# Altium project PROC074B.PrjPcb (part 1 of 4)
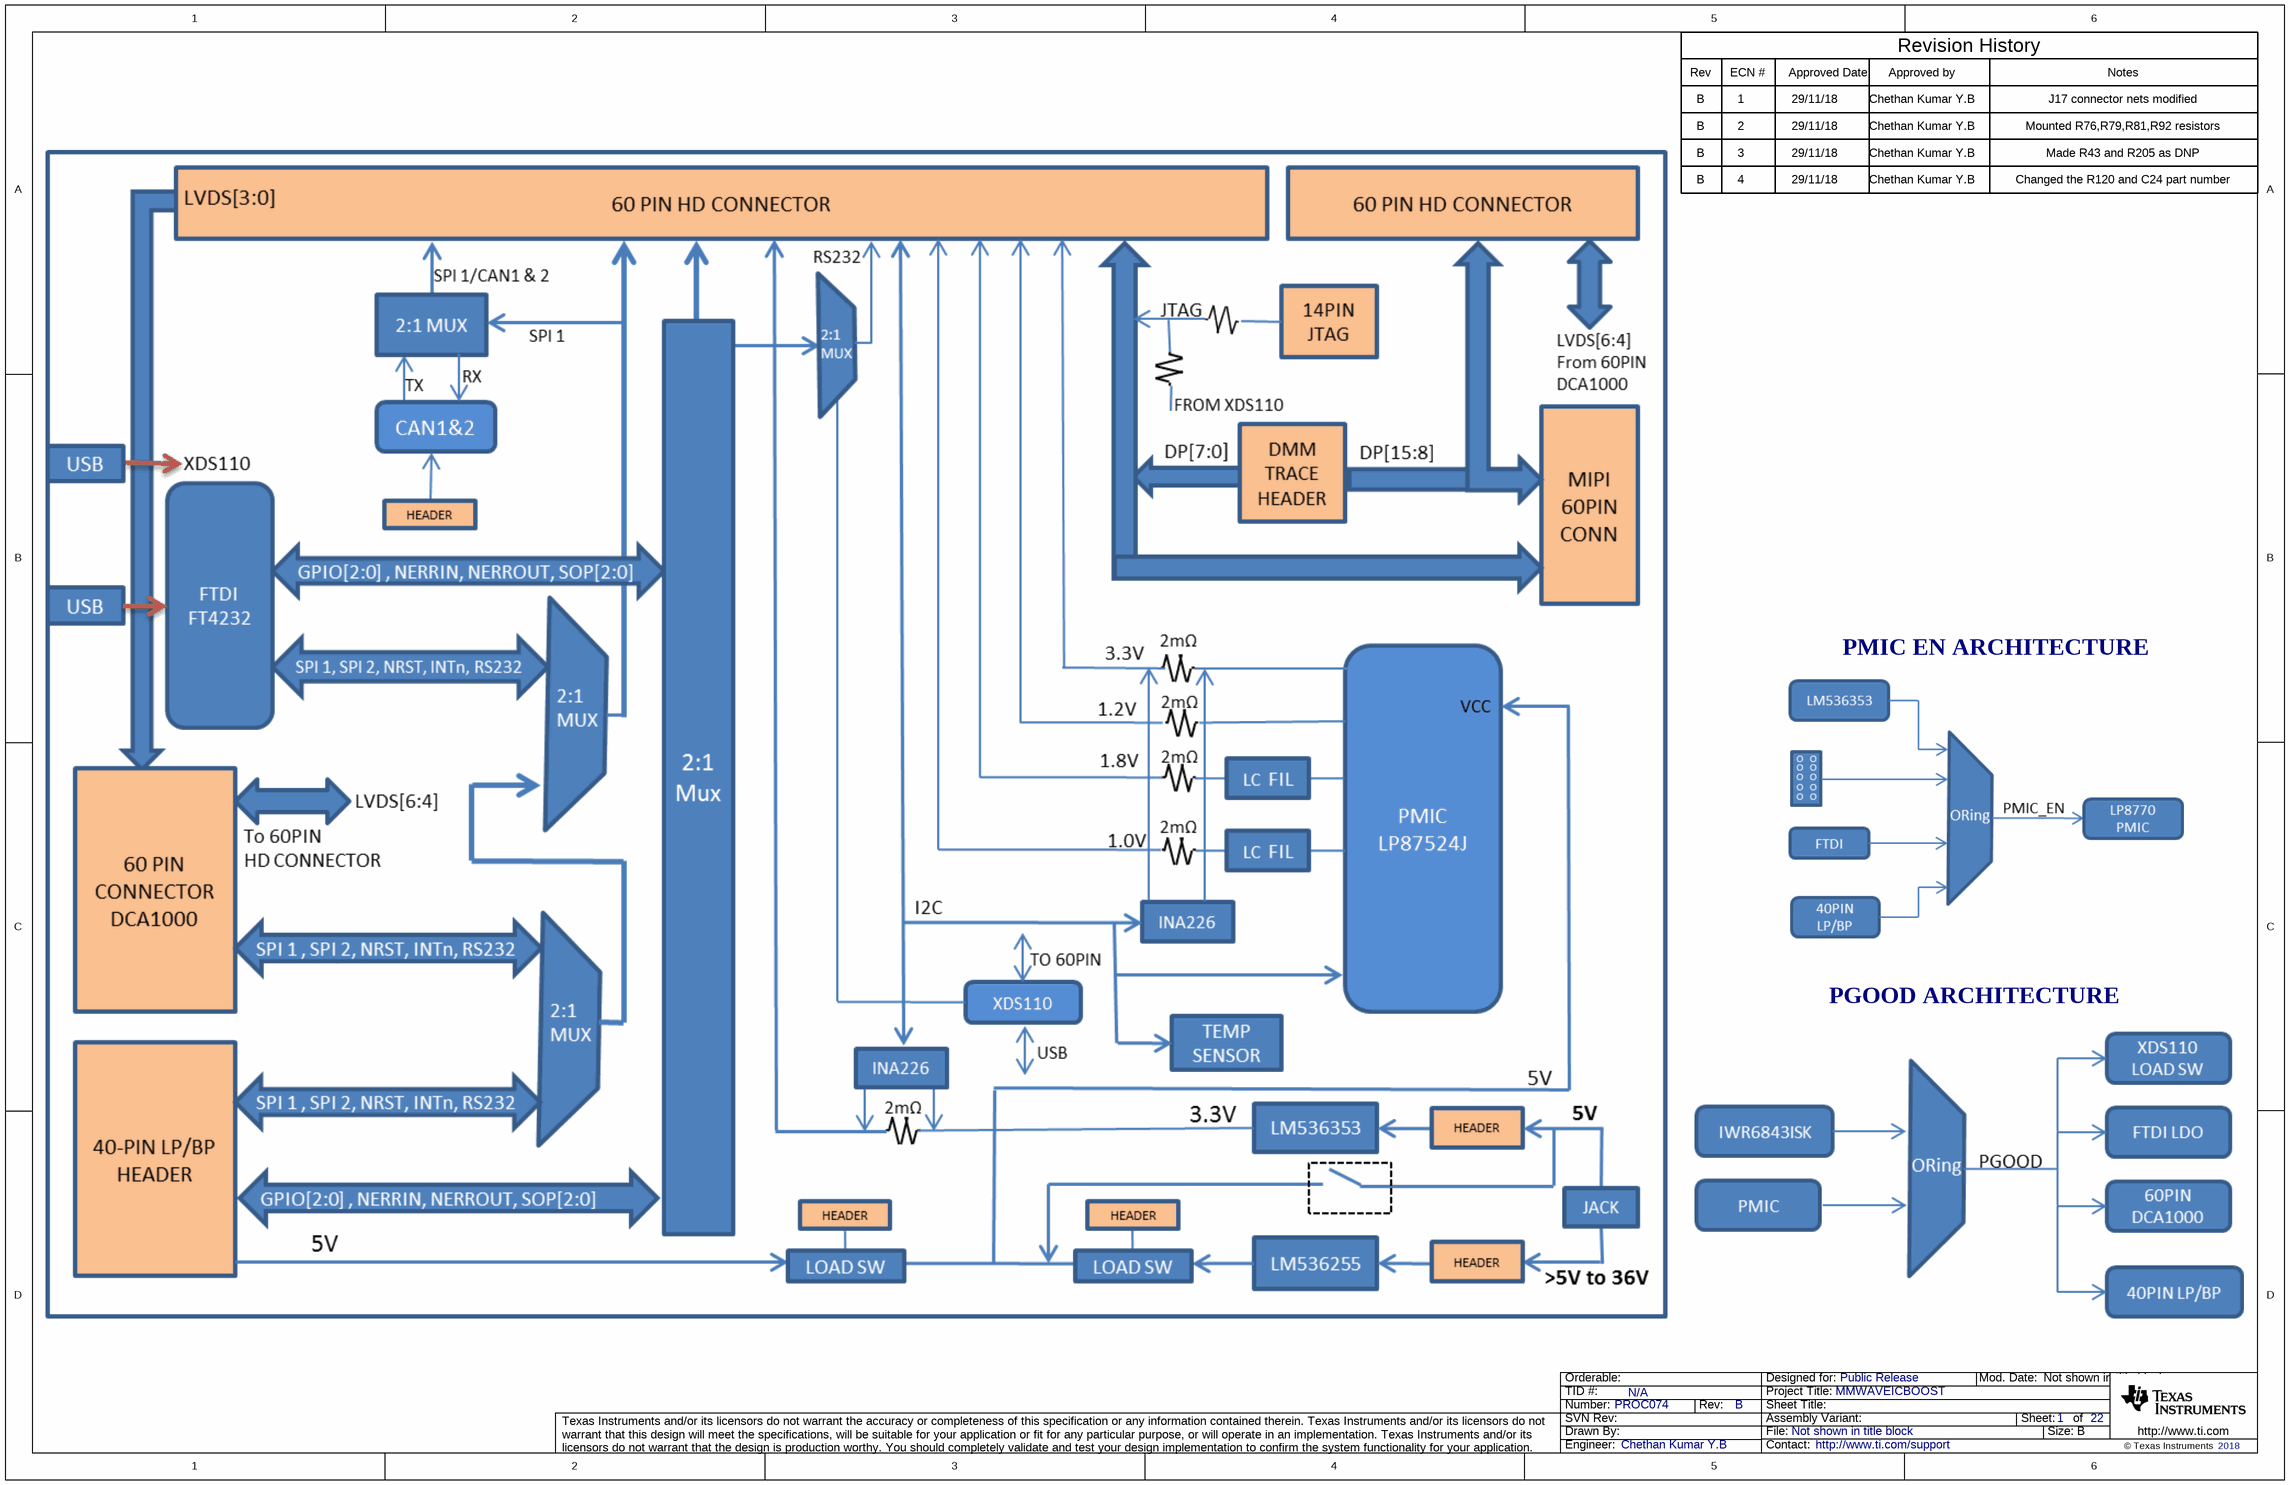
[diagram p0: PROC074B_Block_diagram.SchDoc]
CopyrightYear: 2018; PCB_Layout: TESSOLVE; PCB_Rev: B; PRJ_Customer: Public Release; PRJ_Engineer: Chethan Kumar Y.B; PRJ_Number: PROC074; PRJ_Title: MMWAVEICBOOST; SCH_Rev: B; TechSupport: http://www.ti.com/support; TID: N/A
22 sheets, 600 parts. Net scope: flat (ports and power ports of the same name join across sheets).
Board file: PROC074B-PCB.PcbDoc
Sheets:
  PROC074B_Block_diagram.SchDoc
  PROC074B_Table_Of_Contents.SchDoc
  PROC074B_Muxing_Block_Diagram.SchDoc
  PROC074B_PWR_RST_LEDs.SchDoc
  PROC074B_PWR_INPUT_REG.SchDoc
  PROC074B_Current_Sensors.SchDoc
  PROC074B_LP8752J_PMIC.SchDoc
  PROC074B_LP_Connector.SchDoc
  PROC074B_BP_LP_RNR_Options.SchDoc
  PROC074B_HD_Conn_JTAG_HDR.SchDoc
  PROC074B_XDS110_Interface_1A.SchDoc
  PROC074B_XDS110_Interface_1B.SchDoc
  PROC074B_CAN_Interface.SchDoc
  PROC074B_SOP_Selection.SchDoc
  PROC074B_Temp_Sensor.SchDoc
  PROC074B_FTDI_Interface.SchDoc
  PROC074B_FTDI_Interface_PWR.SchDoc
  PROC074B_CAN_Interface_LEDs.SchDoc
  PROC074B_Analog_Mux_1A.SchDoc
  PROC074B_Analog_Mux_1B.SchDoc
  PROC074B_HD_Connector_DCA.SchDoc
  PROC074B_EVM_Hardware.SchDoc

## Sheet PROC074B_Block_diagram.SchDoc
size 431 x 279 mm; Date: Not shown in title block; ApprovedBy: Not shown in title block; CheckedBy: Not shown in title block; Author: Not shown in title block; CompanyName: Not shown in title block; Engineer: Not shown in title block; Organization: Not shown in title block; Address1: Not shown in title block; Address2: Not shown in title block; Address3: Not shown in title block; Address4: Not shown in title block; DocumentNumber: 1; Revision: Use project parameter SCH_Rev; SheetNumber: 1; SheetTotal: 22; PageSetup: Record=PageOptions¦CenterHorizontal=True¦CenterVertical=True¦PrintScale=1.00¦XCorrection=1.00¦YCorrection=1.00¦PrintKind=0¦BorderSize=5000000¦LeftOffset=0¦BottomOffset=0¦Orientation=2¦PaperLength=1000¦PaperWidth=1000¦Scale=100¦PaperSource=15¦PrintQuality=600¦MediaType=1¦DitherType=10¦PaperKind=Letter¦PrintScaleMode=1

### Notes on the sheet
- Rev
- B
- 1
- ECN #
- 29/11/18
- Approved Date
- Approved by
- Chethan Kumar Y.B
- Revision History
- Notes
- J17 connector nets modified
- 2
- 3
- Mounted R76,R79,R81,R92 resistors
- Made R43 and R205 as DNP
- 4
- Changed the R120 and C24 part number
- PMIC EN ARCHITECTURE
- PGOOD ARCHITECTURE

## Sheet PROC074B_Table_Of_Contents.SchDoc
size 431 x 279 mm; Date: Not shown in title block; ApprovedBy: Not shown in title block; CheckedBy: Not shown in title block; Author: Not shown in title block; CompanyName: Not shown in title block; Engineer: Not shown in title block; Organization: Not shown in title block; Address1: Not shown in title block; Address2: Not shown in title block; Address3: Not shown in title block; Address4: Not shown in title block; DocumentNumber: 1; Revision: Use project parameter SCH_Rev; SheetNumber: 2; SheetTotal: 22; PageSetup: Record=PageOptions¦CenterHorizontal=True¦CenterVertical=True¦PrintScale=1.00¦XCorrection=1.00¦YCorrection=1.00¦PrintKind=0¦BorderSize=5000000¦LeftOffset=0¦BottomOffset=0¦Orientation=2¦PaperLength=1000¦PaperWidth=1000¦Scale=100¦PaperSource=15¦PrintQuality=600¦MediaType=1¦DitherType=10¦PaperKind=Letter¦PrintScaleMode=1
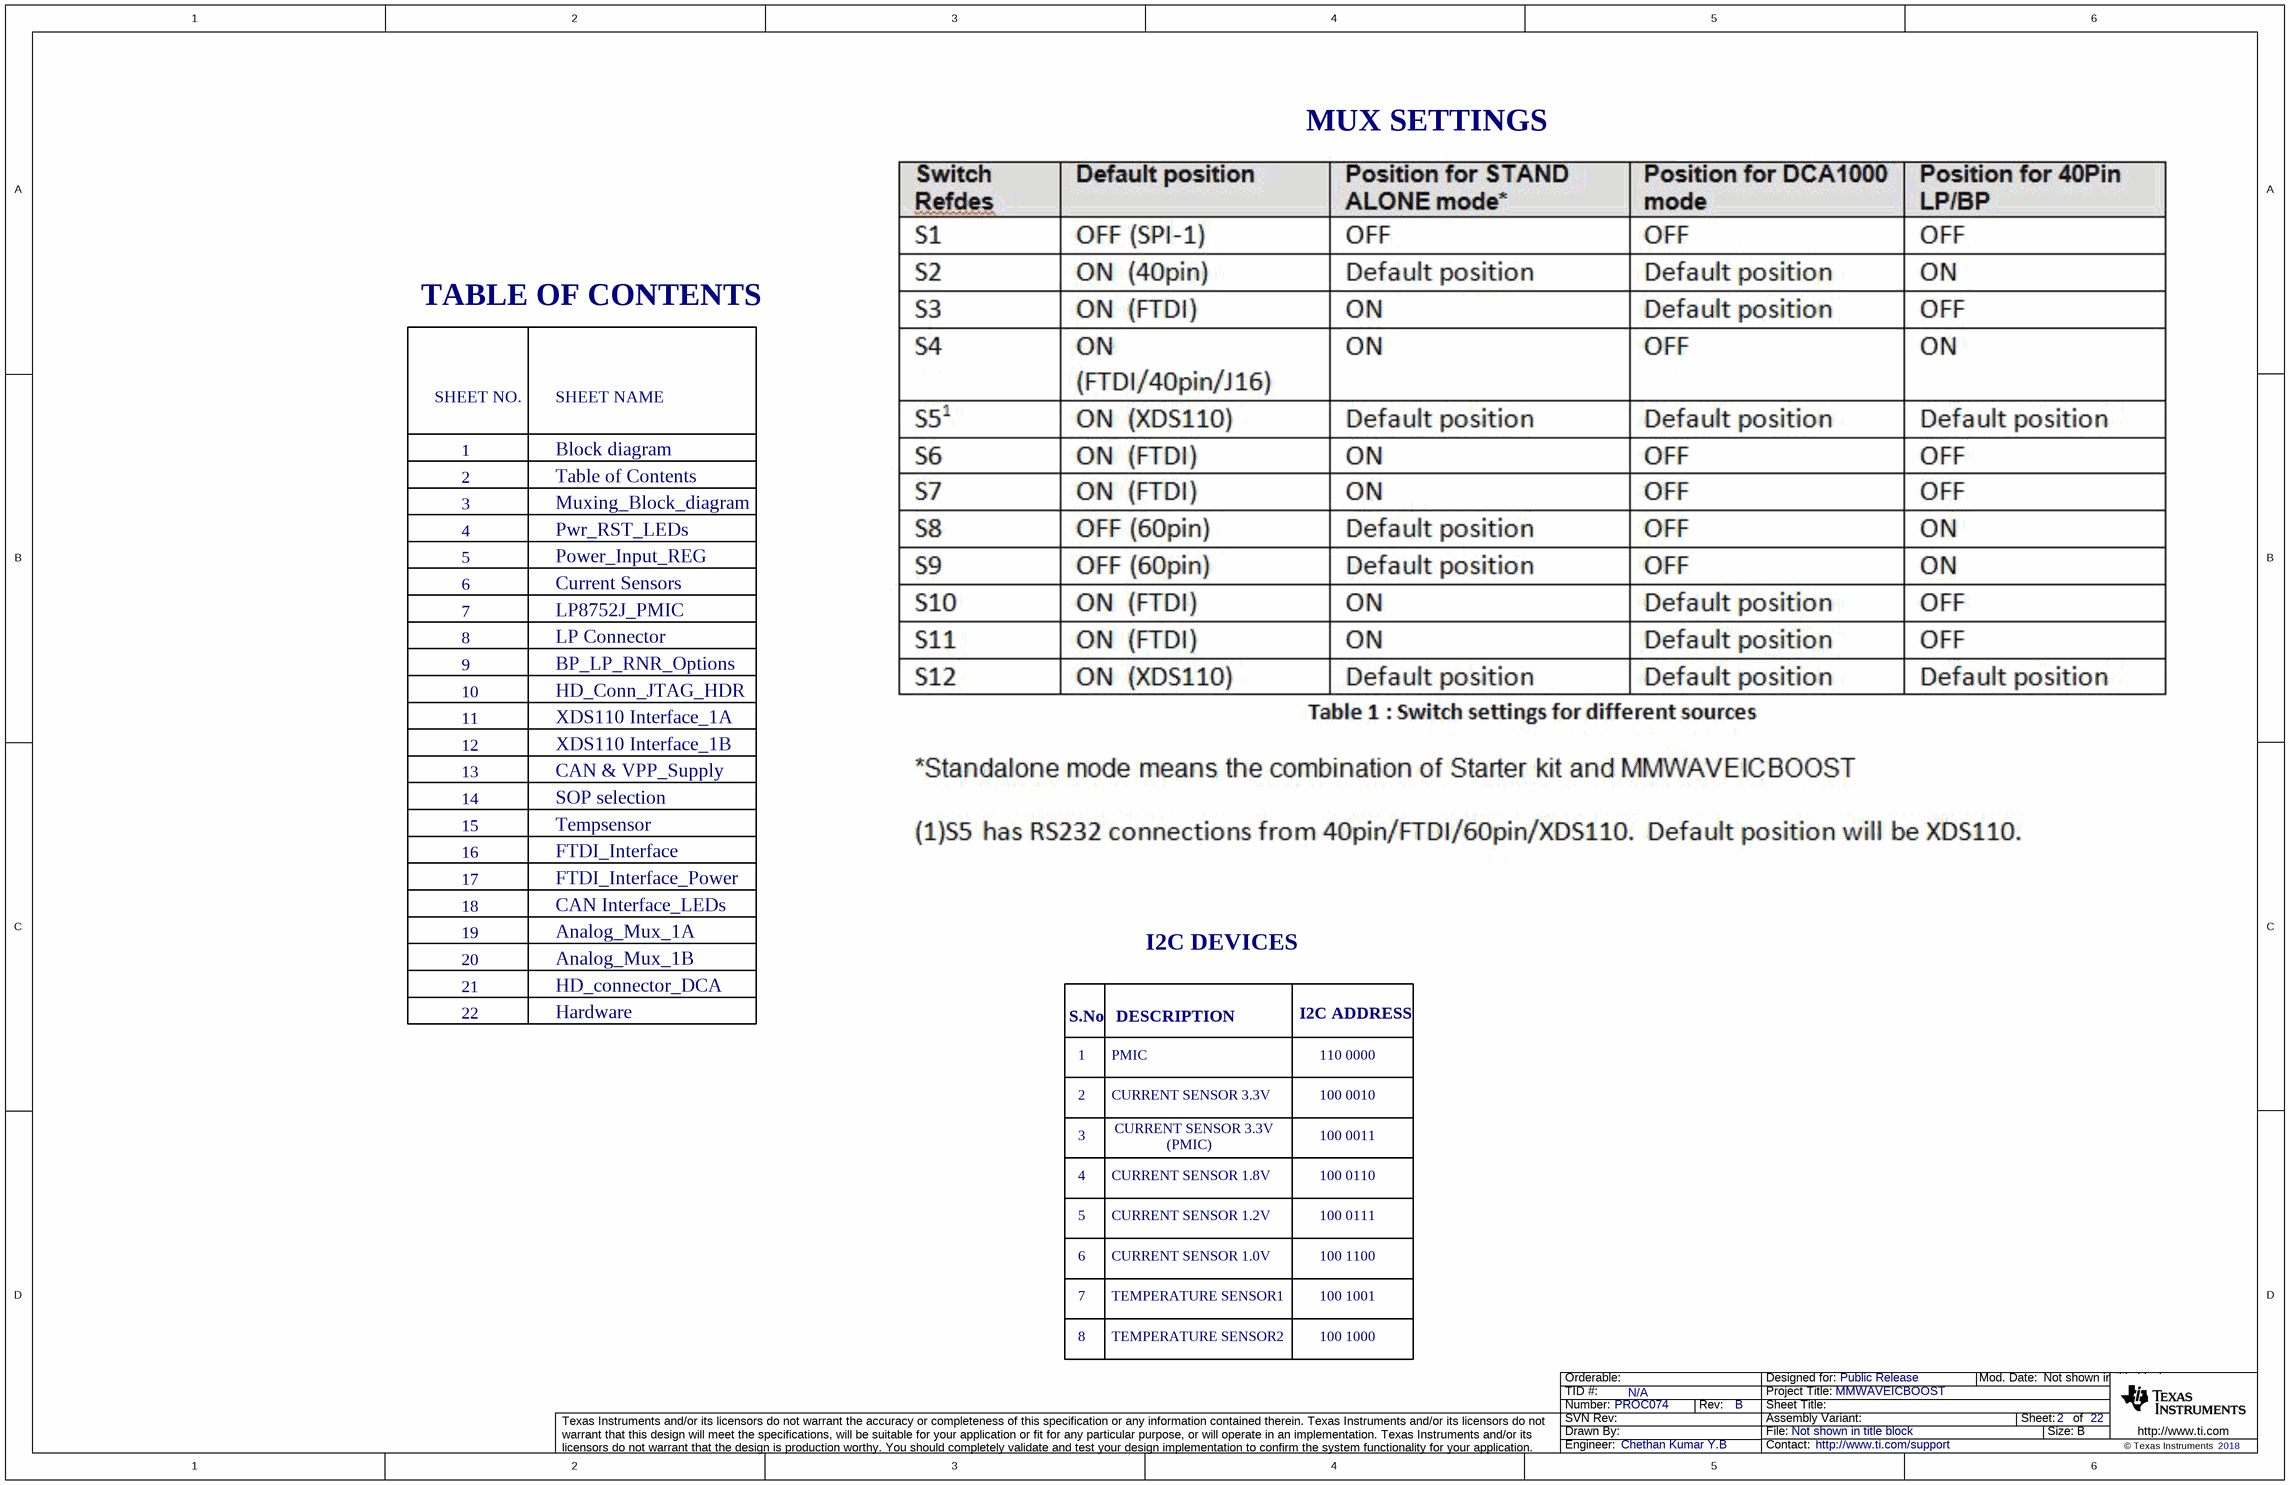
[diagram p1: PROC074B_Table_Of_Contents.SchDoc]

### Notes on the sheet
- MUX SETTINGS
- TABLE OF CONTENTS
- SHEET NO.
- SHEET NAME
- 1
- 2
- Table of Contents
- Block diagram
- 3
- 4
- 5
- Pwr_RST_LEDs
- Power_Input_REG
- Muxing_Block_diagram
- 7
- 6
- Current Sensors
- LP8752J_PMIC
- 8
- 9
- 10
- HD_Conn_JTAG_HDR
- LP Connector
- BP_LP_RNR_Options
- 11
- 12
- XDS110 Interface_1A
- XDS110 Interface_1B
- 13
- 14
- 15
- CAN & VPP_Supply
- SOP selection
- Tempsensor
- 16
- 17
- FTDI_Interface_Power
- FTDI_Interface
- 18
- 19
- 20
- Analog_Mux_1A
- CAN Interface_LEDs
- Analog_Mux_1B
- I2C DEVICES
- 21
- 22
- HD_connector_DCA
- Hardware
- S.No
- DESCRIPTION
- I2C ADDRESS
- PMIC
- CURRENT SENSOR 3.3V
- 100 0010
- 110 0000
- (PMIC)
- 100 0011
- CURRENT SENSOR 1.8V
- CURRENT SENSOR 1.2V
- 100 0110
- 100 0111
- CURRENT SENSOR 1.0V
- TEMPERATURE SENSOR1
- 100 1100
- 100 1001
- TEMPERATURE SENSOR2
- 100 1000

## Sheet PROC074B_Muxing_Block_Diagram.SchDoc
size 431 x 279 mm; Date: Not shown in title block; ApprovedBy: Not shown in title block; CheckedBy: Not shown in title block; Author: Not shown in title block; CompanyName: Not shown in title block; Engineer: Not shown in title block; Organization: Not shown in title block; Address1: Not shown in title block; Address2: Not shown in title block; Address3: Not shown in title block; Address4: Not shown in title block; DocumentNumber: 1; Revision: Use project parameter SCH_Rev; SheetNumber: 3; SheetTotal: 22; PageSetup: Record=PageOptions¦CenterHorizontal=True¦CenterVertical=True¦PrintScale=1.00¦XCorrection=1.00¦YCorrection=1.00¦PrintKind=0¦BorderSize=5000000¦LeftOffset=0¦BottomOffset=0¦Orientation=2¦PaperLength=1000¦PaperWidth=1000¦Scale=100¦PaperSource=15¦PrintQuality=600¦MediaType=1¦DitherType=10¦PaperKind=Letter¦PrintScaleMode=1
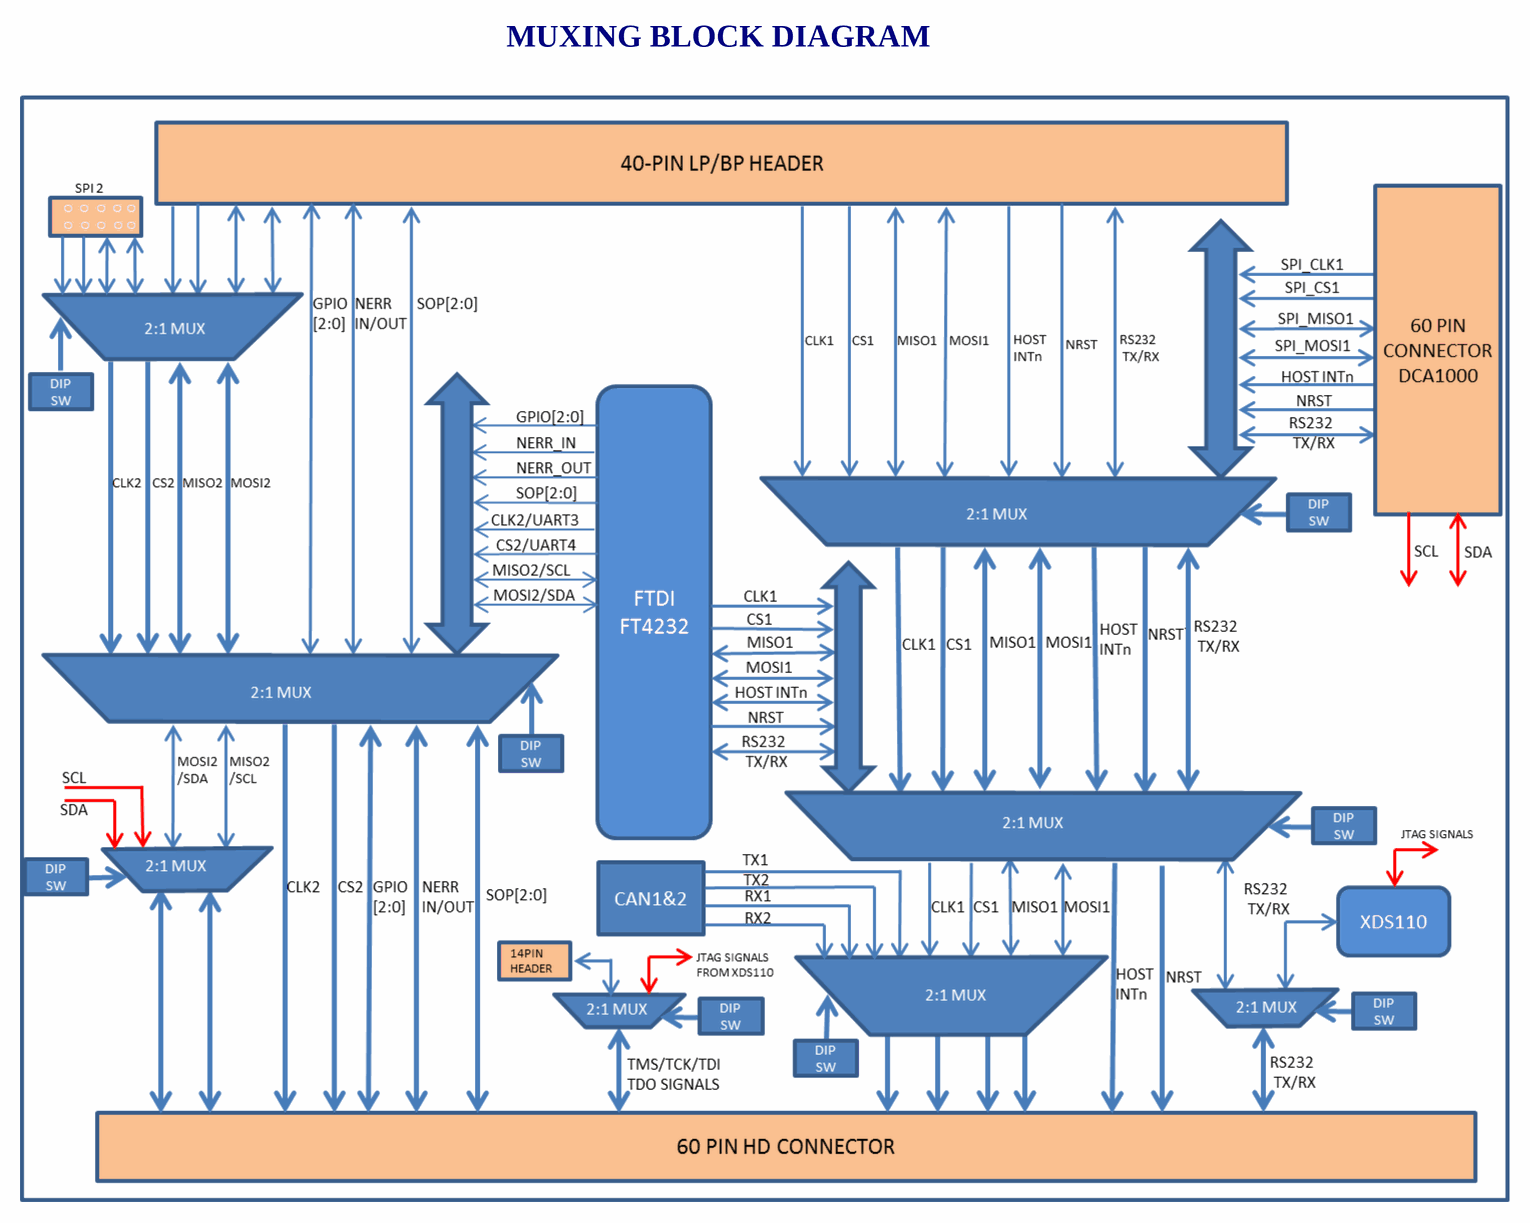
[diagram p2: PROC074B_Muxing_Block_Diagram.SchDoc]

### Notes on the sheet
- MUXING BLOCK DIAGRAM

## Sheet PROC074B_PWR_RST_LEDs.SchDoc
size 431 x 279 mm; Date: Not shown in title block; ApprovedBy: Not shown in title block; CheckedBy: Not shown in title block; Author: Not shown in title block; CompanyName: Not shown in title block; Engineer: Not shown in title block; Organization: Not shown in title block; Address1: Not shown in title block; Address2: Not shown in title block; Address3: Not shown in title block; Address4: Not shown in title block; DocumentNumber: 1; Revision: Use project parameter SCH_Rev; SheetNumber: 4; SheetTotal: 22; PageSetup: Record=PageOptions¦CenterHorizontal=True¦CenterVertical=True¦PrintScale=1.00¦XCorrection=1.00¦YCorrection=1.00¦PrintKind=0¦BorderSize=5000000¦LeftOffset=0¦BottomOffset=0¦Orientation=2¦PaperLength=1000¦PaperWidth=1000¦Scale=100¦PaperSource=15¦PrintQuality=600¦MediaType=1¦DitherType=10¦PaperKind=Letter¦PrintScaleMode=1
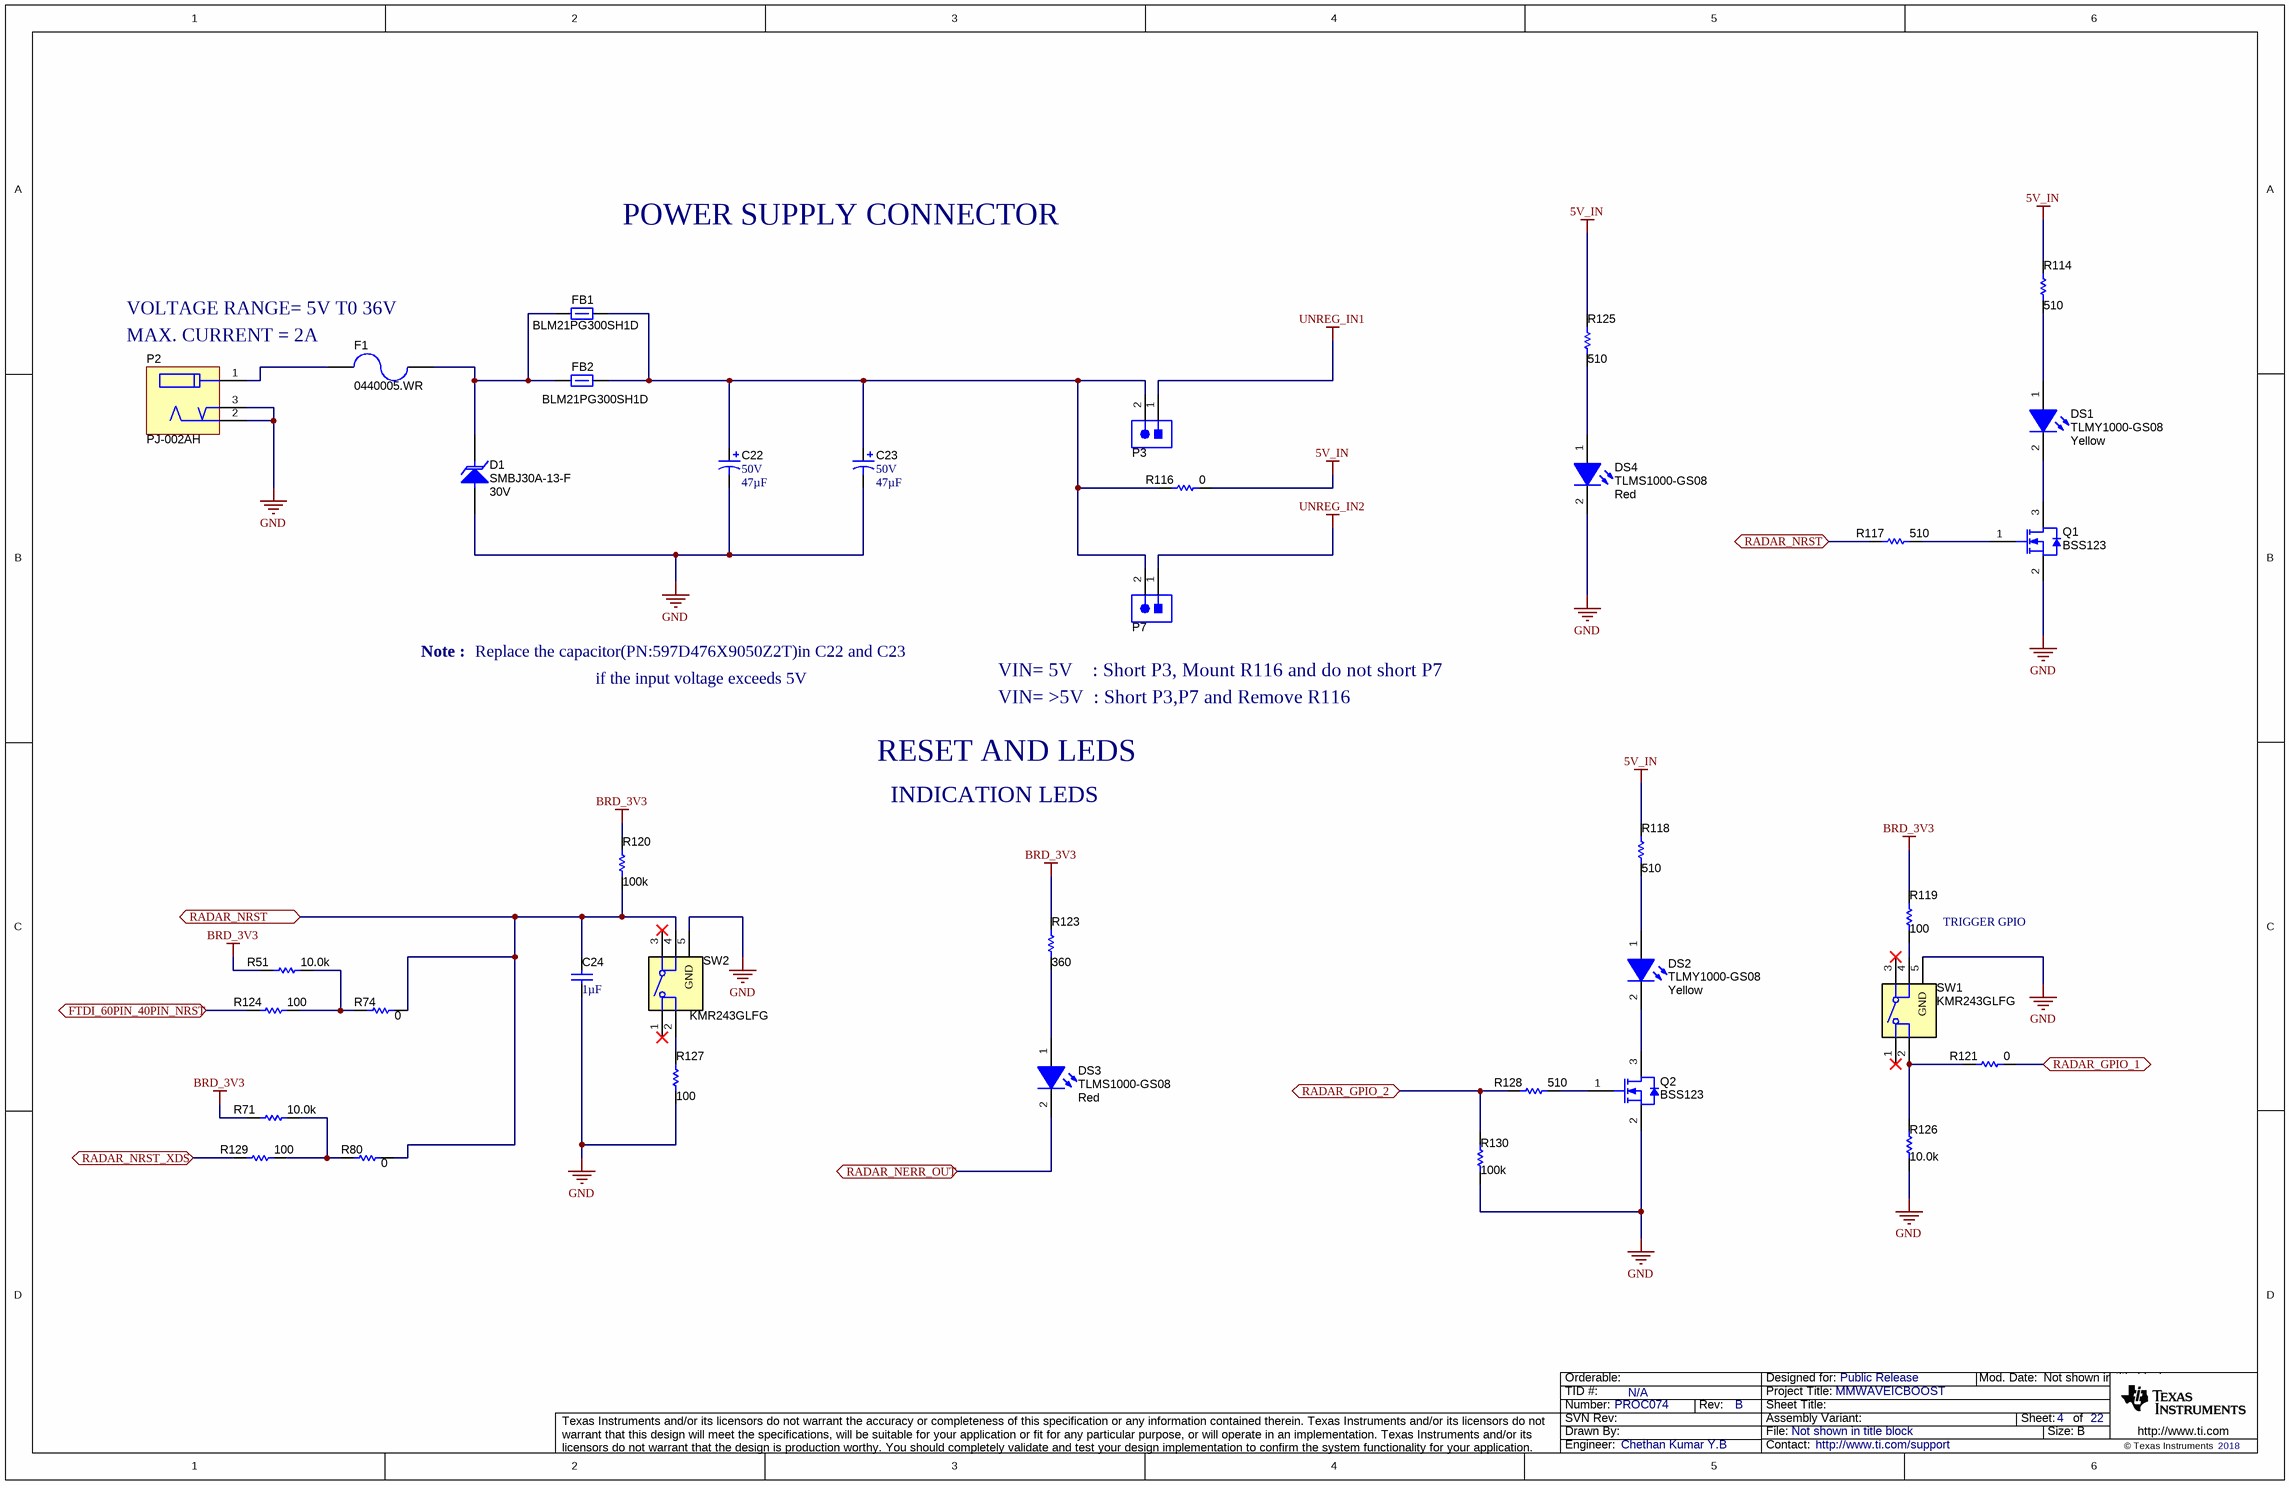
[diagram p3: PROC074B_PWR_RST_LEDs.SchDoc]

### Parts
C22  VDC_V: 50V  ValueDisplayed: 47µF  [597D_Z]  (hidden comment: 597D476X9050Z2T)
C23  VDC_V: 50V  ValueDisplayed: 47µF  [597D_Z]  (hidden comment: 597D476X9050Z2T)
C24  ValueDisplayed: 1µF  [0402L]  (hidden comment: CL05A105KA5NQNC)
D1  SMBJ30A-13-F  value 30V  [SMB]
DS1  TLMY1000-GS08  value Yellow  [TLMx1000_Yellow]
DS2  TLMY1000-GS08  value Yellow  [TLMx1000_Yellow]
DS3  TLMS1000-GS08  value Red  [TLMx1000_Red]
DS4  TLMS1000-GS08  value Red  [TLMx1000_Red]
F1  0440005.WR  [1206]
FB1  BLM21PG300SH1D  [0805_HV]
FB2  BLM21PG300SH1D  [0805_HV]
P2  PJ-002AH  [CUI_PJ-002AH]
P3  TSW-102-07-G-S  [TSW-102-07-X-S]  (value not drawn)
P7  TSW-102-07-G-S  [TSW-102-07-X-S]  (value not drawn)
Q1  BSS123  [SOT-23]
Q2  BSS123  [SOT-23]
R51  ValueDisplayed: 10.0k  [0402L]  (hidden comment: CRCW040210K0FKED)
R71  ValueDisplayed: 10.0k  [0402L]  (hidden comment: CRCW040210K0FKED)
R74  ValueDisplayed: 0  [0402L]  (hidden comment: ERJ-2GE0R00X)
R80  ValueDisplayed: 0  [0402L]  (hidden comment: ERJ-2GE0R00X)
R114  ValueDisplayed: 510  [0402L]  (hidden comment: ERJ-2GEJ511X)
R116  ValueDisplayed: 0  [2010]  (hidden comment: CRCW20100000Z0EF)
R117  ValueDisplayed: 510  [0402L]  (hidden comment: ERJ-2GEJ511X)
R118  ValueDisplayed: 510  [0402L]  (hidden comment: ERJ-2GEJ511X)
R119  ValueDisplayed: 100  [0402L]  (hidden comment: ERJ-2GEJ101X)
R120  ValueDisplayed: 100k  [0402L]  (hidden comment: CRCW0402100KFKED)
R121  ValueDisplayed: 0  [0201_Silk]  (hidden comment: CRCW02010000Z0ED)
R123  ValueDisplayed: 360  [0402L]  (hidden comment: ERJ-2GEJ361X)
R124  ValueDisplayed: 100  [0402L]  (hidden comment: ERJ-2GEJ101X)
R125  ValueDisplayed: 510  [0402L]  (hidden comment: ERJ-2GEJ511X)
R126  ValueDisplayed: 10.0k  [0402L]  (hidden comment: CRCW040210K0FKED)
R127  ValueDisplayed: 100  [0402L]  (hidden comment: ERJ-2GEJ101X)
R128  ValueDisplayed: 510  [0402L]  (hidden comment: ERJ-2GEJ511X)
R129  ValueDisplayed: 100  [0402L]  (hidden comment: ERJ-2GEJ101X)
R130  ValueDisplayed: 100k  [0402L]  (hidden comment: CRCW0402100KFKED)
SW1  KMR243GLFG  [SW_KMR243GLFG]
SW2  KMR243GLFG  [SW_KMR243GLFG]

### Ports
FTDI_60PIN_40PIN_NRST, RADAR_GPIO_1, RADAR_GPIO_2, RADAR_NERR_OUT, RADAR_NRST, RADAR_NRST_XDS

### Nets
5V_IN: R114.2 R116.2 R118.2 R125.2
BRD_3V3: R51.2 R71.2 R119.2 R120.2 R123.2
GND: C22.2(-) C23.2(-) C24.1 D1.2(A) DS4.2(K) P2.2 P2.3 Q1.2(S) Q2.2(S) R126.1 R127.1 R130.1 SW1.5(GND) SW2.5(GND)
UNREG_IN1: P3.1
UNREG_IN2: P7.1
FTDI_60PIN_40PIN_NRST: R124.1 ; port FTDI_60PIN_40PIN_NRST
RADAR_GPIO_1: R121.2 ; port RADAR_GPIO_1
RADAR_GPIO_2: R128.1 R130.2 ; port RADAR_GPIO_2
RADAR_NERR_OUT: DS3.2(K) ; port RADAR_NERR_OUT
RADAR_NRST: C24.2 R74.1 R80.1 R117.1 R120.1 SW2.4 ; port RADAR_NRST
RADAR_NRST_XDS: R129.1 ; port RADAR_NRST_XDS
NetC22_1: C22.1(+) C23.1(+) FB1.2 FB2.2 P3.2 P7.2 R116.1
NetD1_1: D1.1(K) F1.1 FB1.1 FB2.1
NetDS1_1: DS1.1(A) R114.1
NetDS1_2: DS1.2(K) Q1.3(D)
NetDS2_1: DS2.1(A) R118.1
NetDS2_2: DS2.2(K) Q2.3(D)
NetDS3_1: DS3.1(A) R123.1
NetDS4_1: DS4.1(A) R125.1
NetF1_2: F1.2 P2.1
NetQ1_1: Q1.1(G) R117.2
NetQ2_1: Q2.1(G) R128.2
NetR51_1: R51.1 R74.2 R124.2
NetR71_1: R71.1 R80.2 R129.2
NetR119_1: R119.1 SW1.4
NetR121_1: R121.1 R126.2 SW1.2
NetR127_2: R127.2 SW2.2

Not connected (* = marked no-connect by the designer): SW1 1* 3*; SW2 1* 3*

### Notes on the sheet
- POWER SUPPLY CONNECTOR
- VOLTAGE RANGE= 5V T0 36V
- (near P2) MAX. CURRENT = 2A
- Note :
- Replace the capacitor(PN:597D476X9050Z2T)in C22 and C23
- if the input voltage exceeds 5V
- VIN= >5V  : Short P3,P7 and Remove R116
- VIN= 5V    : Short P3, Mount R116 and do not short P7
- RESET AND LEDS
- INDICATION LEDS
- (near R119) TRIGGER GPIO

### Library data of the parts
C22 C23 = CMP-0082253-1: CAP, TA, 47 µF, 50 V, +/- 10%, 0.24 ohm, SMD; Manufacturer: Vishay-Sprague; IRMS_A: 1.1A; SizeAreaWB_mm2: 76.8; SizeArea_mm2: 45.6; AEC Qualified: N; AEC Category: Q200; Value: 47uF; TaMax_C: 125°C; SizeZ_mm: 6.4; Polarized: Y; TaMin_C: -55°C; SizeY_mm: 6; CompType: Capacitor; SizeX_mm: 7.6; ESR_ohm: 2.4d; Cap_Case: 7.6x6x6.4mm
C24 = CMP-0085848-1: CAP, CERM, 1 µF, 25 V,+/- 10%, X5R, 0402; Manufacturer: Samsung Electro-Mechanics; SizeZ_mm: 0.6; AEC Category: Q200; Value: 1uF; SizeArea_mm2: 0.5; TaMax_C: 85°C; TaMin_C: -55°C; SizeX_mm: 1; Cap_Case: 0402; AEC Qualified: N; U/M: EA; Value2: 25V; CompType: Capacitor; SizeAreaWB_mm2: 3
D1 = CMP-0005561-2: Diode, TVS, Uni, 30 V, 48.4 Vc, SMB; Manufacturer: Diodes Inc.; Power_W: 5W; SizeAreaWB_mm2: 44.156; U/M: EA; SizeZ_mm: 2.6; SizeX_mm: 5.6; SizeY_mm: 3.81; SizeArea_mm2: 21.336; AEC Category: Q101
DS1 DS2 = CMP-0078196-1: LED, Yellow, SMD; Manufacturer: Vishay-Semiconductor; Tjmax_C: 120°C; SizeAreaWB_mm2: 4.68; Vr_V: 6V; Power_TotalModule: 40mW; Angle: 160; SizeArea_mm2: 1.28; Ir_A: 10µA; SizeZ_mm: 0.65; Io_A: 2mA; Vf_V: 1.8V; SizeY_mm: 0.8; U/M: EA; Value1: .04W; SizeX_mm: 1.6; Type: AlInGaP
DS3 DS4 = CMP-0078197-1: LED, Red, SMD; Manufacturer: Vishay-Semiconductor; Tjmax_C: 120°C; SizeAreaWB_mm2: 4.68; Vr_V: 6V; Power_TotalModule: 40mW; Angle: 160; SizeArea_mm2: 1.28; Ir_A: 10µA; SizeZ_mm: 0.65; Io_A: 2mA; Vf_V: 1.8V; SizeY_mm: 0.8; U/M: EA; Value1: .04W; SizeX_mm: 1.6; Type: AlInGaP
F1 = CMP-0003458-1: Fuse, 5 A, 32VAC/VDC, SMD; Manufacturer: Littelfuse; Irating_A: 5A; SizeAreaWB_mm2: 10.92; Interrupt_AC: 50A; VAC_V: 32V; SizeZ_mm: 1.35; SizeX_mm: 3.2; SizeY_mm: 1.6; SizeArea_mm2: 5.12; Rtyp_Ohm: 0.012; MeltingTyp: 4.761
FB1 = CMP-0003364-1: Ferrite Bead, 30 ohm @ 100 MHz, 4 A, 0805; Manufacturer: MuRata; ZTyp@100MHz_Ohm: 30; SizeAreaWB_mm2: 6.75; DCR_ohm: 0.014; Value1: 0.014 ohm; Value: 30 ohm; Imax_A: 4A; SizeZ_mm: 1.45; SizeX_mm: 2; SizeY_mm: 1.25; SizeArea_mm2: 2.5; INSTALLATION: DNP
FB2 = CMP-0003364-1: Ferrite Bead, 30 ohm @ 100 MHz, 4 A, 0805; Manufacturer: MuRata; ZTyp@100MHz_Ohm: 30; SizeAreaWB_mm2: 6.75; DCR_ohm: 0.014; Value1: 0.014 ohm; Value: 30 ohm; Imax_A: 4A; SizeZ_mm: 1.45; SizeX_mm: 2; SizeY_mm: 1.25; SizeArea_mm2: 2.5
P2 = CMP-0078270-1: DC POWER JACK, R/A, TH; Manufacturer: CUI Inc.; Gender: Female; Cert_UL: Y; Current_A: 5A; Voltage_V: 24V; Green_REACh: Incomplete; Green_Lifecycle: Not Set
P3 P7 = CMP-0075405-1: Header, 100mil, 2x1, Gold, TH; Manufacturer: Samtec; Pitch_mm: 2.54; Cert_VDE: N; Gender: Male; Cert_CSA: Y; Voltage_V: 550V; Green_REACh: Passed; Current_A: 6.3A; CT: False; Green_Lifecycle: Active; Row_Count: 1; CNHeader: True
Q1 Q2 = CMP-0000947-2: MOSFET, N-CH, 100 V, 0.17 A, SOT-23; Alternate Manufacturer: None; Manufacturer: Fairchild Semiconductor; SizeZ_mm: 1.1; ChType: N; Value2: 1.8 nC; Value1: 1; VdsMax_V: 100V; SizeX_mm: 2.5; SizeY_mm: 3; Vgs_V: 20V; Value: 100V; Rdson45_ohm: 10; SizeArea_mm2: 7.5; AEC Category: Q101; IdsMax_A: 1.7dA; SizeAreaWB_mm2: 14; U/M: EA; QgTyp_nC: 1.8
R51 R71 R126 = CMP-0025958-2: RES, 10.0 k, 1%, 0.063 W, 0402; Manufacturer: Vishay-Dale; Power_W: 63mW; TempCo: 100 ppm/C; Value_Code: 10k0; U/M: EA; Value: 10.0k; EIA_Code: E96; Res_ohm: 10k; SizeX_mm: 1; SizeY_mm: 0.5; SizeZ_mm: 0.6; Value2: 0.063W; VDC_V: 50V; AEC Category: Q200
R74 R80 = CMP-0026992-2: RES, 0, 5%, 0.063 W, 0402; Manufacturer: Panasonic; Power_W: 63mW; TempCo: 600 ppm/C; Value_Code: 0000; U/M: EA; Value: 0; EIA_Code: E24; SizeX_mm: 1; SizeY_mm: 0.5; SizeZ_mm: 0.6; Value2: 0.063W; VDC_V: 50V; AEC Category: Q200
R114 R117 R118 R125 R128 = CMP-0078212-1: RES, 510, 5%, 0.1 W, AEC-Q200 Grade 0, 0402; Manufacturer: Panasonic; Value_Code: 510R; SizeArea_mm2: 0.5; AEC Qualified: Y; AEC Category: Q200; Value: 510; SizeZ_mm: 0.6; EIA_Code: E24; TempCo: 200 ppm/C; AEC Grade: 0; Power_W: 100mW; VDC_V: 50V; Value2: 0.1W; U/M: EA; SizeX_mm: 1
R116 = CMP-0016044-2: RES, 0, 5%, 0.75 W, AEC-Q200 Grade 0, 2010; Manufacturer: Vishay-Dale; Power_W: 750mW; TempCo: ppm/C; Value_Code: 0000; U/M: EA; Value: 0; EIA_Code: E24; SizeX_mm: 5; SizeY_mm: 2.5; SizeZ_mm: 1.66; Value2: 0.75W; SizeArea_mm2: 12.5; AEC Qualified: Y; AEC Category: Q200
R119 R124 R127 R129 = CMP-0026993-2: RES, 100, 5%, 0.1 W, AEC-Q200 Grade 0, 0402; Manufacturer: Panasonic; Power_W: 100mW; TempCo: 200 ppm/C; Value_Code: 100R; U/M: EA; Value: 100; EIA_Code: E24; SizeX_mm: 1; SizeY_mm: 0.5; SizeZ_mm: 0.6; Value2: 0.1W; AEC Qualified: Y; AEC Grade: 0; AEC Category: Q200
R120 = CMP-0025950-2: RES, 100 k, 1%, 0.063 W, 0402; Manufacturer: Vishay-Dale; Power_W: 63mW; TempCo: 100 ppm/C; U/M: EA; Value: 100k; EIA_Code: E96; SizeX_mm: 1; SizeY_mm: 0.5; SizeZ_mm: 0.6; Value2: 0.063W; CompType: Resistor; VDC_V: 50V; AEC Category: Q200
R121 = CMP-0027008-3: RES, 0, 5%, 0.05 W, 0201; Manufacturer: Vishay-Dale; Power_W: 50mW; TempCo: ppm/C; Value_Code: 0000; U/M: EA; Value: 0; EIA_Code: E24; SizeX_mm: 0.6; SizeY_mm: 0.3; SizeZ_mm: 0.26; Value2: 0.05W; SizeArea_mm2: 0.18; AEC Qualified: N; AEC Category: Q200
R123 = CMP-0078194-1: RES, 360, 5%, 0.1 W, AEC-Q200 Grade 0, 0402; Manufacturer: Panasonic; Value_Code: 360R; SizeArea_mm2: 0.5; AEC Qualified: Y; AEC Category: Q200; Value: 360; SizeZ_mm: 0.6; EIA_Code: E24; TempCo: 200 ppm/C; AEC Grade: 0; Power_W: 100mW; VDC_V: 50V; Value2: 0.1W; U/M: EA; SizeX_mm: 1
R130 = CMP-0025950-2: RES, 100 k, 1%, 0.063 W, 0402; Manufacturer: Vishay-Dale; Power_W: 63mW; TempCo: 100 ppm/C; U/M: EA; Value: 100k; EIA_Code: E96; SizeX_mm: 1; SizeY_mm: 0.5; SizeZ_mm: 0.6; Value2: 0.063W; VDC_V: 50V; AEC Category: Q200
SW1 SW2 = CMP-0002325-1: Switch, SPST-NO, Off-Mom, 0.01 A, 32 VDC, SMD; Manufacturer: C&K Components; CurrentRating_mA: 10A; PositionCount: 1; SizeX_mm: 4.6; SizeY_mm: 2.8; SizeZ_mm: 1.9; SizeArea_mm2: 12.88; VDC_V: 32V; SizeAreaWB_mm2: 21.28

## Sheet PROC074B_PWR_INPUT_REG.SchDoc
size 431 x 279 mm; Date: Not shown in title block; ApprovedBy: Not shown in title block; CheckedBy: Not shown in title block; Author: Not shown in title block; CompanyName: Not shown in title block; Engineer: Not shown in title block; Organization: Not shown in title block; Address1: Not shown in title block; Address2: Not shown in title block; Address3: Not shown in title block; Address4: Not shown in title block; DocumentNumber: 1; Revision: Use project parameter SCH_Rev; SheetNumber: 5; SheetTotal: 22; PageSetup: Record=PageOptions¦CenterHorizontal=True¦CenterVertical=True¦PrintScale=1.00¦XCorrection=1.00¦YCorrection=1.00¦PrintKind=0¦BorderSize=5000000¦LeftOffset=0¦BottomOffset=0¦Orientation=2¦PaperLength=1000¦PaperWidth=1000¦Scale=100¦PaperSource=15¦PrintQuality=600¦MediaType=1¦DitherType=10¦PaperKind=Letter¦PrintScaleMode=1
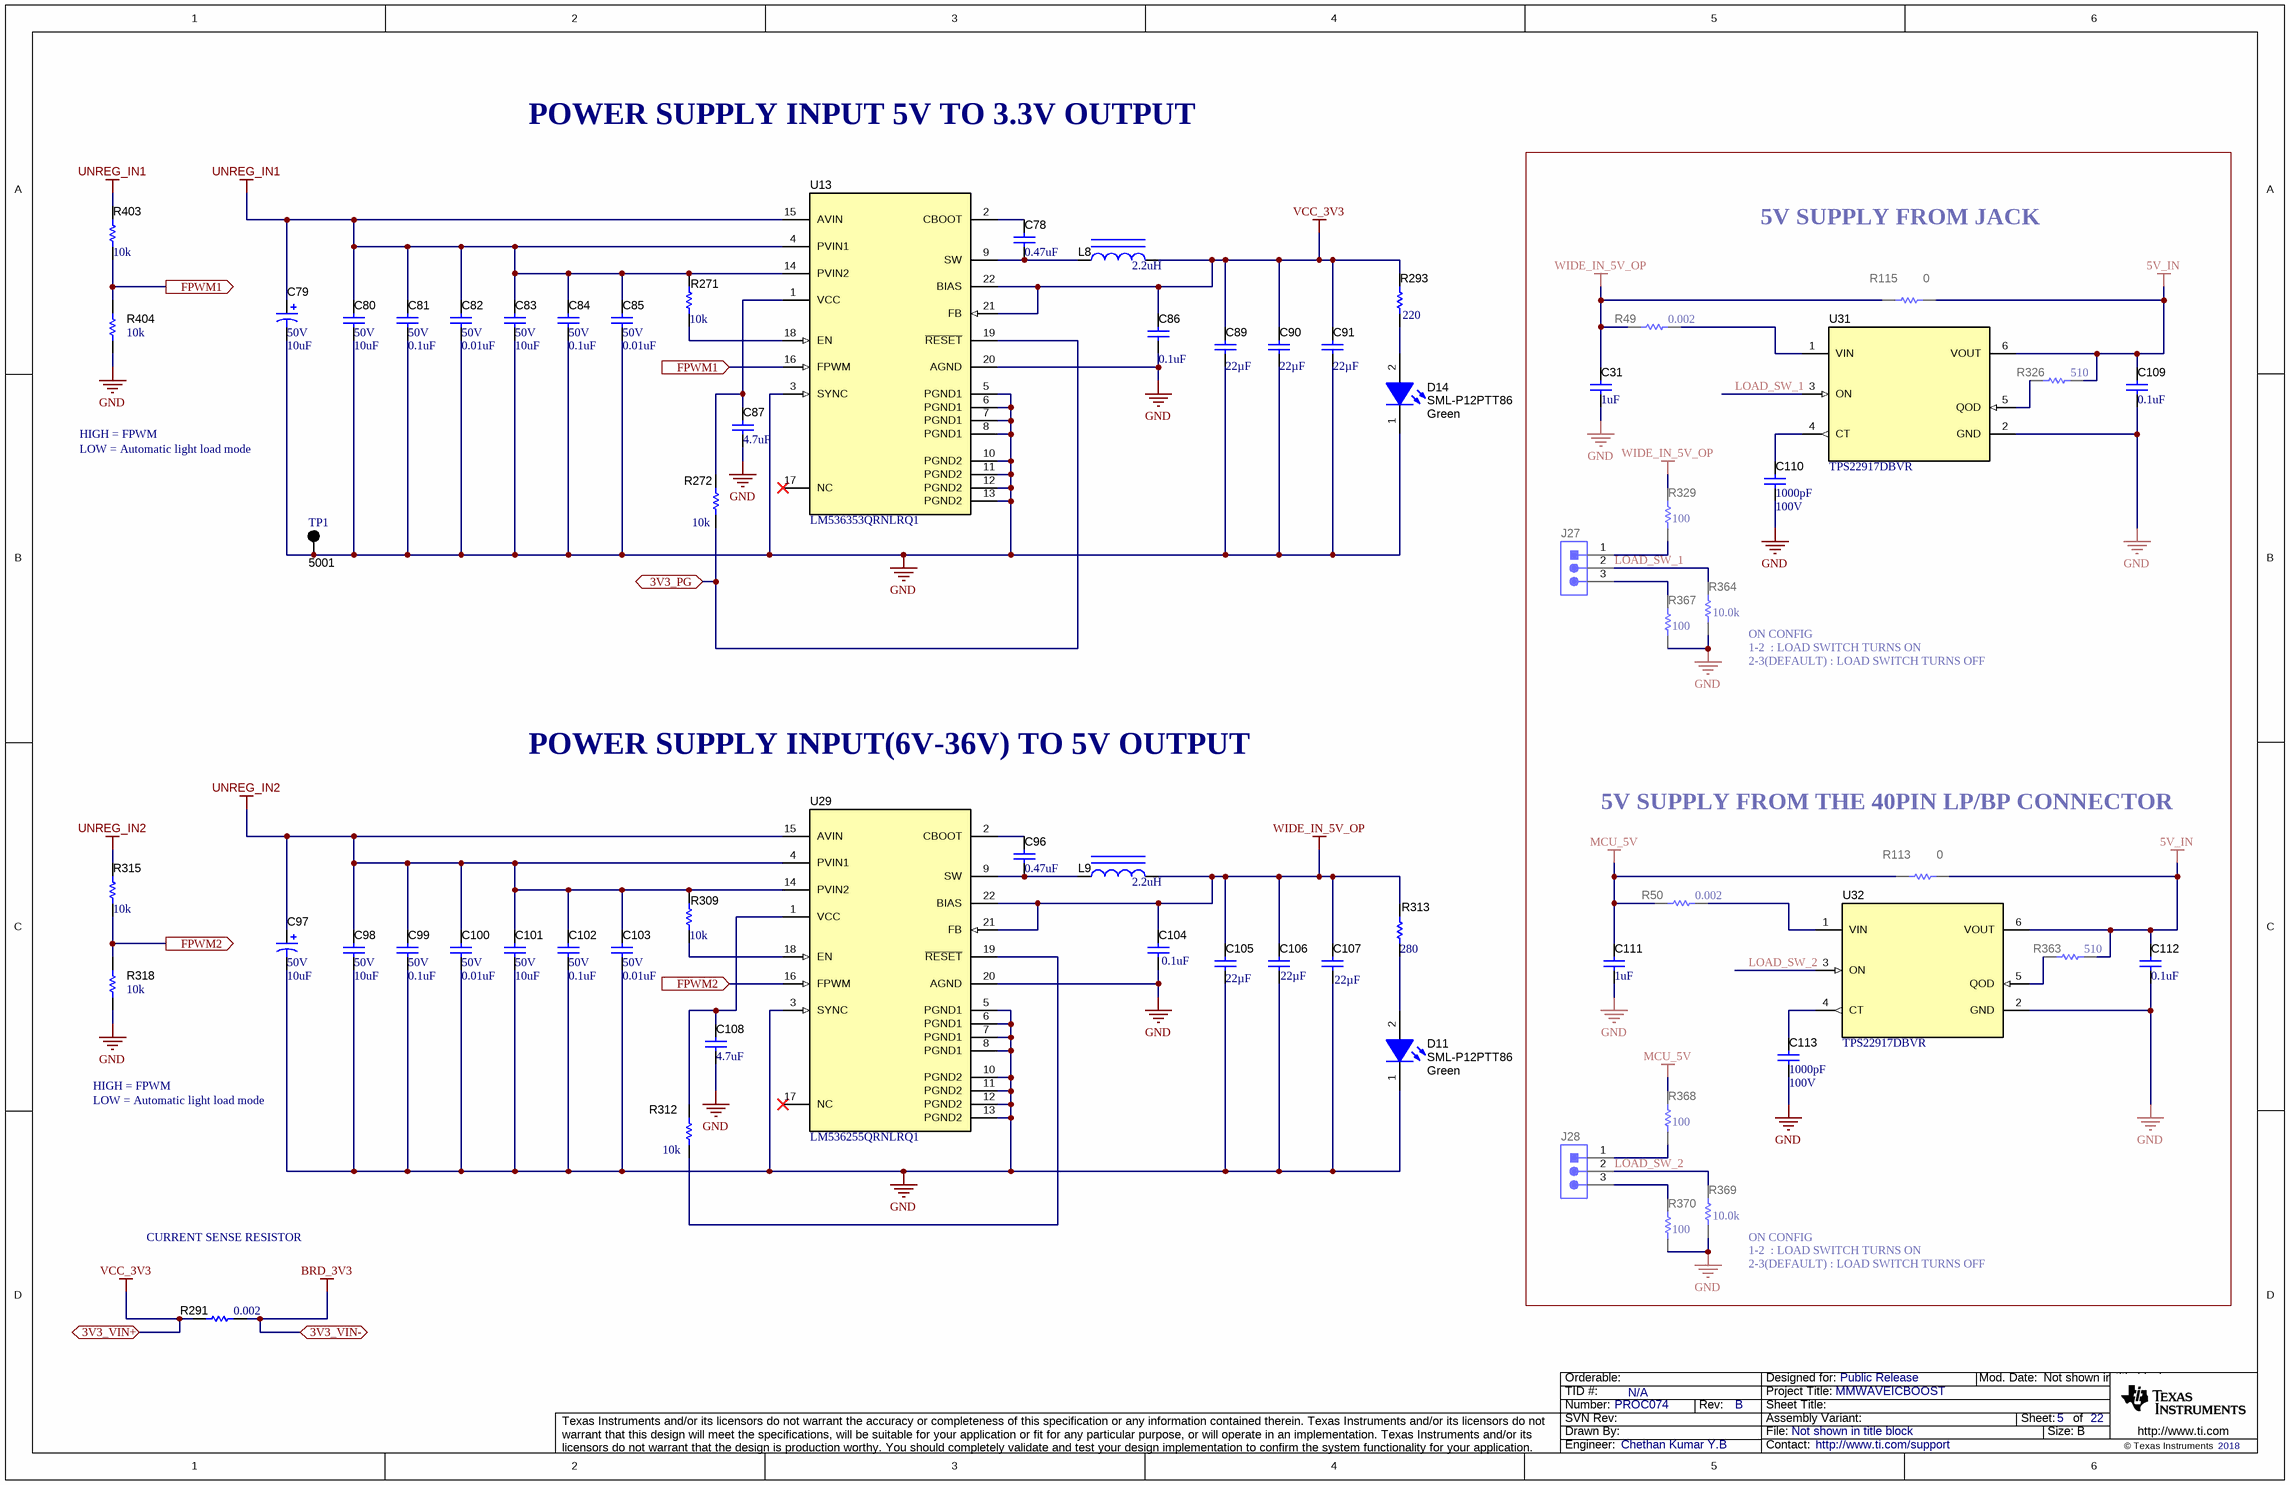
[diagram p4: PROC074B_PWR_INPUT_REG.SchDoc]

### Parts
C31  ValueDisplayed: 1uF  [0603]  (hidden comment: GCM188R71C105KA64D)
C78  ValueDisplayed: 0.47uF  [0402]  (hidden comment: JMK105B7474KVHF)
C79  VDC_V: 50V  ValueDisplayed: 10uF  [SM_RADIAL_C]  (hidden comment: EEE-FK1H100UR)
C80  VDC_V: 50V  ValueDisplayed: 10uF  [1210_270]  (hidden comment: GRM32ER71H106MA12)
C81  VDC_V: 50V  ValueDisplayed: 0.1uF  [1210]  (hidden comment: C1210C104K5RACTU)
C82  VDC_V: 50V  ValueDisplayed: 0.01uF  [0805_HV]  (hidden comment: C0805C103K5RACTU)
C83  VDC_V: 50V  ValueDisplayed: 10uF  [1210_270]  (hidden comment: GRM32ER71H106MA12)
C84  VDC_V: 50V  ValueDisplayed: 0.1uF  [1210]  (hidden comment: C1210C104K5RACTU)
C85  VDC_V: 50V  ValueDisplayed: 0.01uF  [0805_HV]  (hidden comment: C0805C103K5RACTU)
C86  ValueDisplayed: 0.1uF  [0402]  (hidden comment: 0402YC104KAT2A)
C87  ValueDisplayed: 4.7uF  [0805_HV]  (hidden comment: C2012X7R1E475K125AB)
C89  ValueDisplayed: 22µF  [1210_270]  (hidden comment: CL32B226KOJNFNE)
C90  ValueDisplayed: 22µF  [1210_270]  (hidden comment: CL32B226KOJNFNE)
C91  ValueDisplayed: 22µF  [1210_270]  (hidden comment: CL32B226KOJNFNE)
C96  ValueDisplayed: 0.47uF  [0402]  (hidden comment: JMK105B7474KVHF)
C97  VDC_V: 50V  ValueDisplayed: 10uF  [SM_RADIAL_C]  (hidden comment: EEE-FK1H100UR)
C98  VDC_V: 50V  ValueDisplayed: 10uF  [1210_270]  (hidden comment: GRM32ER71H106MA12)
C99  VDC_V: 50V  ValueDisplayed: 0.1uF  [1210]  (hidden comment: C1210C104K5RACTU)
C100  VDC_V: 50V  ValueDisplayed: 0.01uF  [0805_HV]  (hidden comment: C0805C103K5RACTU)
C101  VDC_V: 50V  ValueDisplayed: 10uF  [1210_270]  (hidden comment: GRM32ER71H106MA12)
C102  VDC_V: 50V  ValueDisplayed: 0.1uF  [1210]  (hidden comment: C1210C104K5RACTU)
C103  VDC_V: 50V  ValueDisplayed: 0.01uF  [0805_HV]  (hidden comment: C0805C103K5RACTU)
C104  ValueDisplayed: 0.1uF  [0402]  (hidden comment: 0402YC104KAT2A)
C105  ValueDisplayed: 22µF  [1210_270]  (hidden comment: CL32B226KOJNFNE)
C106  ValueDisplayed: 22µF  [1210_270]  (hidden comment: CL32B226KOJNFNE)
C107  ValueDisplayed: 22µF  [1210_270]  (hidden comment: CL32B226KOJNFNE)
C108  ValueDisplayed: 4.7uF  [0805_HV]  (hidden comment: C2012X7R1E475K125AB)
C109  ValueDisplayed: 0.1uF  [0603]  (hidden comment: C0603C104J3RACTU)
C110  VDC_V: 100V  ValueDisplayed: 1000pF  [0402]  (hidden comment: CGA2B3X7S2A102K050BB)
C111  ValueDisplayed: 1uF  [0603]  (hidden comment: GCM188R71C105KA64D)
C112  ValueDisplayed: 0.1uF  [0603]  (hidden comment: C0603C104J3RACTU)
C113  VDC_V: 100V  ValueDisplayed: 1000pF  [0402]  (hidden comment: CGA2B3X7S2A102K050BB)
D11  SML-P12PTT86  value Green  [SML-P1_GREEN]
D14  SML-P12PTT86  value Green  [SML-P1_GREEN]
J27  22284033  [Molex_0022284033]  (value not drawn)
J28  22284033  [Molex_0022284033]  (value not drawn)
L8  ValueDisplayed: 2.2uH  [XAL5030]  (hidden comment: XAL5030-222MEB)
L9  ValueDisplayed: 2.2uH  [XAL5030]  (hidden comment: XAL5030-222MEB)
R49  ValueDisplayed: 0.002  [1206]  (hidden comment: PMR18EZPFV2L00)
R50  ValueDisplayed: 0.002  [1206]  (hidden comment: PMR18EZPFV2L00)
R113  ValueDisplayed: 0  [2010]  (hidden comment: CRCW20100000Z0EF)
R115  ValueDisplayed: 0  [2010]  (hidden comment: CRCW20100000Z0EF)
R271  ValueDisplayed: 10k  [0402]  (hidden comment: CRCW040210K0JNED)
R272  ValueDisplayed: 10k  [0402]  (hidden comment: CRCW040210K0JNED)
R291  ValueDisplayed: 0.002  [1206]  (hidden comment: PMR18EZPFV2L00)
R293  ValueDisplayed: 220  [0402]  (hidden comment: CRCW0402220RJNED)
R309  ValueDisplayed: 10k  [0402]  (hidden comment: CRCW040210K0JNED)
R312  ValueDisplayed: 10k  [0402]  (hidden comment: CRCW040210K0JNED)
R313  ValueDisplayed: 280  [0402]  (hidden comment: CRCW0402280RFKED)
R315  ValueDisplayed: 10k  [0402]  (hidden comment: CRCW040210K0JNED)
R318  ValueDisplayed: 10k  [0402]  (hidden comment: CRCW040210K0JNED)
R326  ValueDisplayed: 510  [0402]  (hidden comment: CRCW0402510RJNED)
R329  ValueDisplayed: 100  [0402]  (hidden comment: ERJ-2GEJ101X)
R363  ValueDisplayed: 510  [0402]  (hidden comment: CRCW0402510RJNED)
R364  ValueDisplayed: 10.0k  [0402]  (hidden comment: CRCW040210K0FKED)
R367  ValueDisplayed: 100  [0402]  (hidden comment: ERJ-2GEJ101X)
R368  ValueDisplayed: 100  [0402]  (hidden comment: ERJ-2GEJ101X)
R369  ValueDisplayed: 10.0k  [0402]  (hidden comment: CRCW040210K0FKED)
R370  ValueDisplayed: 100  [0402]  (hidden comment: ERJ-2GEJ101X)
R403  ValueDisplayed: 10k  [0402]  (hidden comment: CRCW040210K0JNED)
R404  ValueDisplayed: 10k  [0402]  (hidden comment: CRCW040210K0JNED)
TP1  5001  [Keystone5001]
U13  LM536353QRNLRQ1  [RNL0022A]
U29  LM536255QRNLRQ1  [RNL0022A]
U31  TPS22917DBVR  [DBV0006A_L]
U32  TPS22917DBVR  [DBV0006A_L]

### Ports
3V3_PG, 3V3_VIN+, 3V3_VIN-, FPWM1 (in), FPWM1 (out), FPWM2 (in), FPWM2 (out)

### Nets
5V_IN: C109.1 C112.1 R113.2 R115.2 R326.1 R363.1 U31.6(VOUT) U32.6(VOUT)
BRD_3V3: R291.2 ; port 3V3_VIN-
GND: C31.2 C79.2(-) C80.2 C81.2 C82.2 C83.2 C84.2 C85.2 C86.2 C87.2 C89.2 C90.2 C91.2 C97.2(-) C98.2 C99.2 C100.2 C101.2 C102.2 C103.2 C104.2 C105.2 C106.2 C107.2 C108.2 C109.2 C110.2 C111.2 C112.2 C113.2 D11.1(K) D14.1(K) R318.1 R364.1 R367.1 R369.1 R370.1 R404.1 TP1.1 U13.3(SYNC) U13.5(PGND1) U13.6(PGND1) U13.7(PGND1) U13.8(PGND1) U13.10(PGND2) U13.11(PGND2) U13.12(PGND2) U13.13(PGND2) U13.20(AGND) U29.3(SYNC) U29.5(PGND1) U29.6(PGND1) U29.7(PGND1) U29.8(PGND1) U29.10(PGND2) U29.11(PGND2) U29.12(PGND2) U29.13(PGND2) U29.20(AGND) U31.2(GND) U32.2(GND)
MCU_5V: C111.1 R50.1 R113.1 R368.2
UNREG_IN1: C79.1(+) C80.1 C81.1 C82.1 C83.1 C84.1 C85.1 R271.2 R403.2 U13.4(PVIN1) U13.14(PVIN2) U13.15(AVIN)
UNREG_IN2: C97.1(+) C98.1 C99.1 C100.1 C101.1 C102.1 C103.1 R309.2 R315.2 U29.4(PVIN1) U29.14(PVIN2) U29.15(AVIN)
VCC_3V3: C86.1 C89.1 C90.1 C91.1 L8.2 R291.1 R293.2 U13.21(FB) U13.22(BIAS) ; port 3V3_VIN+
WIDE_IN_5V_OP: C31.1 C104.1 C105.1 C106.1 C107.1 L9.2 R49.1 R115.1 R313.2 R329.2 U29.21(FB) U29.22(BIAS)
3V3_PG: R272.2 U13.19(~{RESET}) ; port 3V3_PG
FPWM1: R403.1 R404.2 U13.16(FPWM) ; port FPWM1
FPWM2: R315.1 R318.2 U29.16(FPWM) ; port FPWM2
LOAD_SW_1: J27.2 R364.2 U31.3(ON)
LOAD_SW_2: J28.2 R369.2 U32.3(ON)
NetC78_1: C78.1 U13.2(CBOOT)
NetC78_2: C78.2 L8.1 U13.9(SW)
NetC87_1: C87.1 R272.1 U13.1(VCC)
NetC96_1: C96.1 U29.2(CBOOT)
NetC96_2: C96.2 L9.1 U29.9(SW)
NetC108_1: C108.1 R312.1 U29.1(VCC)
NetC110_1: C110.1 U31.4(CT)
NetC113_1: C113.1 U32.4(CT)
NetD11_2: D11.2(A) R313.1
NetD14_2: D14.2(A) R293.1
NetJ27_1: J27.1 R329.1
NetJ27_3: J27.3 R367.2
NetJ28_1: J28.1 R368.1
NetJ28_3: J28.3 R370.2
NetR49_2: R49.2 U31.1(VIN)
NetR50_2: R50.2 U32.1(VIN)
NetR271_1: R271.1 U13.18(EN)
NetR309_1: R309.1 U29.18(EN)
NetR312_2: R312.2 U29.19(~{RESET})
NetR326_2: R326.2 U31.5(QOD)
NetR363_2: R363.2 U32.5(QOD)

Not connected (* = marked no-connect by the designer): U13 17(NC)*; U29 17(NC)*

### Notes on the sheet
- POWER SUPPLY INPUT 5V TO 3.3V OUTPUT
- 5V SUPPLY FROM JACK
- HIGH = FPWM
- LOW = Automatic light load mode
- (near R364) ON CONFIG
- (near R364) 2-3(DEFAULT) : LOAD SWITCH TURNS OFF
- (near R364) 1-2  : LOAD SWITCH TURNS ON
- POWER SUPPLY INPUT(6V-36V) TO 5V OUTPUT
- 5V SUPPLY FROM THE 40PIN LP/BP CONNECTOR
- CURRENT SENSE RESISTOR
- (near R369) ON CONFIG
- (near R369) 2-3(DEFAULT) : LOAD SWITCH TURNS OFF
- (near R369) 1-2  : LOAD SWITCH TURNS ON

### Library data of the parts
C31 C111 = CMP-0007136-5: CAP, CERM, 1 uF, 16 V, +/- 10%, X7R, AEC-Q200 Grade 1, 0603; Manufacturer: MuRata; TaMin_C: -55°C; Polarized: N; SizeAreaWB_mm2: 4.68; Value1: Unknown; U/M: EA; Value: 1uF; TaMax_C: 125°C; SizeZ_mm: 1; SizeX_mm: 1.6; SizeY_mm: 0.8; Value2: 16V; SizeArea_mm2: 1.28; CompType: Capacitor; AEC Qualified: Y; Cap_F: 1µF; AEC Category: Q200
C78 C96 = CMP-0006717-2: CAP, CERM, 0.47 uF, 6.3 V, +/- 10%, X7R, 0402; Manufacturer: Taiyo Yuden; TaMin_C: -55°C; Polarized: N; SizeAreaWB_mm2: 3; Value1: Unknown; U/M: EA; Value: 0.47uF; TaMax_C: 125°C; SizeZ_mm: 0.6; SizeX_mm: 1; SizeY_mm: 0.5; Value2: 6.3V; CompType: Capacitor; Cap_F: 470nF; AEC Category: Q200
C79 C97 = CMP-0011176-2: CAP, AL, 10 uF, 50 V, +/- 20%, 1.52 ohm, AEC-Q200 Grade 2, SMD; Manufacturer: Panasonic; TaMin_C: -55°C; ESR_ohm: 1.52; Polarized: Y; SizeAreaWB_mm2: 62.05; U/M: EA; Value: 10uF; TaMax_C: 105°C; SizeZ_mm: 5.4; SizeX_mm: 6.5; SizeY_mm: 5.3; Cap_Case: C; SizeArea_mm2: 34.45; CompType: Capacitor; Cap_F: 10µF; IRMS_A: 85mA; AEC Grade: 2; AEC Category: Q200
C80 C83 C98 C101 = CMP-0009227-2: CAP, CERM, 10 uF, 50 V, +/- 20%, X7R, 1210; Manufacturer: MuRata; TaMin_C: -55°C; Polarized: N; SizeAreaWB_mm2: 14.7; Value1: Unknown; U/M: EA; Value: 10uF; TaMax_C: 125°C; SizeZ_mm: 2.7; SizeX_mm: 3.2; SizeY_mm: 2.5; Cap_Case: 1210; SizeArea_mm2: 8; Cap_F: 10µF; AEC Category: Q200
C81 C84 C99 C102 = CMP-0009075-1: CAP, CERM, 0.1 uF, 50 V, +/- 10%, X7R, 1210; Manufacturer: Kemet; TaMin_C: -55°C; Polarized: N; SizeAreaWB_mm2: 14.7; Value1: Unknown; U/M: EA; Value: 0.1uF; TaMax_C: 125°C; SizeZ_mm: 1.35; SizeX_mm: 3.2; SizeY_mm: 2.5; SizeArea_mm2: 8; Cap_F: 100nF; AEC Category: Q200
C82 C85 C100 C103 = CMP-0007718-2: CAP, CERM, 0.01 uF, 50 V, +/- 10%, X7R, 0805; Manufacturer: Kemet; TaMin_C: -55°C; ESR_ohm: 1.739; Polarized: N; SizeAreaWB_mm2: 6.75; Value1: 1.739 ohm; U/M: EA; Value: 0.01uF; TaMax_C: 125°C; SizeZ_mm: 1.45; SizeX_mm: 2; SizeY_mm: 1.25; Cap_Case: 0805; SizeArea_mm2: 2.5; Cap_F: 10nF; IRMS_A: 4.11dA; AEC Category: Q200
C86 C104 = CMP-0006201-2: CAP, CERM, 0.1 uF, 16 V, +/- 10%, X7R, 0402; Manufacturer: AVX; TaMin_C: -55°C; Polarized: N; SizeAreaWB_mm2: 3; Value1: Unknown; U/M: EA; Value: 0.1uF; TaMax_C: 125°C; SizeZ_mm: 0.6; SizeX_mm: 1; SizeY_mm: 0.5; Value2: 16V; CompType: Capacitor; Cap_F: 100nF; AEC Category: Q200
C87 C108 = CMP-0007870-2: CAP, CERM, 4.7 uF, 25 V, +/- 10%, X7R, 0805; Manufacturer: TDK; TaMin_C: -55°C; Polarized: N; SizeAreaWB_mm2: 6.75; Value1: Unknown; U/M: EA; Value: 4.7uF; TaMax_C: 125°C; SizeZ_mm: 1.45; SizeX_mm: 2; SizeY_mm: 1.25; Cap_Case: 0805; Value2: 25V; SizeArea_mm2: 2.5; CompType: Capacitor; Cap_F: 4.7µF; AEC Category: Q200
C89-C91 C105-C107 = CMP-0081783-1: CAP, CERM, 22 µF, 16 V,+/- 10%, X7R, 1210; Manufacturer: Samsung; TaMin_C: -55°C; Polarized: N; SizeAreaWB_mm2: 14.7; U/M: EA; Value: 22uF; TaMax_C: 125°C; SizeZ_mm: 2.7; SizeX_mm: 3.2; SizeY_mm: 2.5; Cap_Case: 1210; Value2: 16V; SizeArea_mm2: 8; CompType: Capacitor; AEC Category: Q200
C109 C112 = CMP-0006856-6: CAP, CERM, 0.1 uF, 25 V, +/- 5%, X7R, 0603; Manufacturer: Kemet; TaMin_C: -55°C; Polarized: N; SizeAreaWB_mm2: 4.68; Value1: Unknown; U/M: EA; Value: 0.1uF; TaMax_C: 125°C; SizeZ_mm: 1; SizeX_mm: 1.6; SizeY_mm: 0.8; Value2: 25V; SizeArea_mm2: 1.28; CompType: Capacitor; Cap_F: 100nF; AEC Category: Q200
C110 C113 = CMP-0006332-2: CAP, CERM, 1000 pF, 100 V, +/- 10%, X7S, AEC-Q200 Grade 1, 0402; Manufacturer: TDK; TaMin_C: -55°C; ESR_ohm: 2.71151; Polarized: N; SizeAreaWB_mm2: 3; Value1: 2.71151 ohm; U/M: EA; Value: 1000pF; TaMax_C: 125°C; SizeZ_mm: 0.6; SizeX_mm: 1; SizeY_mm: 0.5; AEC Qualified: Y; Cap_F: 1nF; IRMS_A: 2.64589dA; AEC Category: Q200
D11 D14 = CMP-0002873-1: LED, Green, SMD; Manufacturer: Rohm; Io_A: 20mA; Value1: W; U/M: EA; Vf_V: 2.2V; Type: AlInGaP
J27 J28 = CMP-0055332-1: Header, 2.54mm, 3x1, Tin, TH; Manufacturer: Molex; CNHeader: TRUE; Current_A: 4A; Shrouded: N; Gender: Male; Voltage_V: 250V; Row_Count: 1; Pitch_mm: 2.54; CT: FALSE; Cert_UL: Y
L8 L9 = CMP-0061001-1: Inductor, Shielded, Composite, 2.2 uH, 9.2 A, 0.01 ohm, SMD; Manufacturer: Coilcraft; Isat: 12.9A @ 30% inductance drop; Irms: 9.2A @ 40C rise; Green_Lifecycle: Not Set; SizeAreaWB_mm2: 54.4544; DCR_ohm: 0.01; Green_REACh: Incomplete; Value: 2.2uH; Imax_A: 9.2A; SizeZ_mm: 3.1; SizeX_mm: 5.28; SizeY_mm: 5.48; SizeArea_mm2: 28.9344; Ind_H: 2.2µH; AEC Category: Q200
R49 R50 = CMP-0081623-1: RES, 0.002, 1%, 1 W, AEC-Q200 Grade 0, 1206; Manufacturer: Rohm; Value_Code: 2L000; SizeAreaWB_mm2: 10.92; SizeArea_mm2: 5.12; AEC Qualified: Y; AEC Category: Q200; Res_ohm: 2m; Value: 0.002; SizeZ_mm: 1.35; Green_REACh: Incomplete; TempCo: 100 ppm/C; AEC Grade: 0; Power_W: 1W; SizeY_mm: 1.6; Green_Lifecycle: Active; CompType: Resistor; SizeX_mm: 3.2; INSTALLATION: DNP
R113 R115 = CMP-0016044-2: RES, 0, 5%, 0.75 W, AEC-Q200 Grade 0, 2010; Manufacturer: Vishay-Dale; Power_W: 750mW; TempCo: ppm/C; Value_Code: 0000; U/M: EA; Value: 0; EIA_Code: E24; SizeX_mm: 5; SizeY_mm: 2.5; SizeZ_mm: 1.66; Value2: 0.75W; SizeArea_mm2: 12.5; CompType: Resistor; AEC Qualified: Y; AEC Category: Q200; INSTALLATION: DNP
R271 R272 R309 R312 R315 R403 = CMP-0026825-5: RES, 10 k, 5%, 0.063 W, AEC-Q200 Grade 0, 0402; Manufacturer: Vishay-Dale; Power_W: 63mW; TempCo: 200 ppm/C; Value_Code: 10k0; Value: 10k; EIA_Code: E24; SizeX_mm: 1; SizeY_mm: 0.5; SizeZ_mm: 0.6; Value2: 0.063W; AEC Qualified: Y; VDC_V: 50V; AEC Category: Q200; AEC Grade: 0
R291 = CMP-0081623-1: RES, 0.002, 1%, 1 W, AEC-Q200 Grade 0, 1206; Manufacturer: Rohm; Value_Code: 2L000; SizeAreaWB_mm2: 10.92; SizeArea_mm2: 5.12; AEC Qualified: Y; AEC Category: Q200; Res_ohm: 2m; Value: 0.002; SizeZ_mm: 1.35; Green_REACh: Incomplete; TempCo: 100 ppm/C; AEC Grade: 0; Power_W: 1W; SizeY_mm: 1.6; Green_Lifecycle: Active; SizeX_mm: 3.2
R293 = CMP-0026878-3: RES, 220, 5%, 0.063 W, AEC-Q200 Grade 0, 0402; Manufacturer: Vishay-Dale; Power_W: 63mW; TempCo: 200 ppm/C; Value_Code: 220R; Value: 220; EIA_Code: E24; SizeX_mm: 1; SizeY_mm: 0.5; SizeZ_mm: 0.6; Value2: 0.063W; AEC Qualified: Y; VDC_V: 50V; AEC Category: Q200; AEC Grade: 0
R313 = CMP-0026216-2: RES, 280, 1%, 0.063 W, AEC-Q200 Grade 0, 0402; Manufacturer: Vishay-Dale; Power_W: 63mW; TempCo: 100 ppm/C; Value_Code: 280R; Value: 280; EIA_Code: E96; SizeX_mm: 1; SizeY_mm: 0.5; SizeZ_mm: 0.6; Value2: 0.063W; AEC Qualified: Y; VDC_V: 50V; AEC Category: Q200; AEC Grade: 0
R318 R404 = CMP-0026825-5: RES, 10 k, 5%, 0.063 W, AEC-Q200 Grade 0, 0402; Manufacturer: Vishay-Dale; Power_W: 63mW; TempCo: 200 ppm/C; Value_Code: 10k0; Value: 10k; EIA_Code: E24; SizeX_mm: 1; SizeY_mm: 0.5; SizeZ_mm: 0.6; Value2: 0.063W; CompType: Resistor; AEC Qualified: Y; VDC_V: 50V; AEC Category: Q200; AEC Grade: 0; INSTALLATION: DNP
R326 R363 = CMP-0026944-3: RES, 510, 5%, 0.063 W, AEC-Q200 Grade 0, 0402; Manufacturer: Vishay-Dale; Power_W: 63mW; TempCo: 200 ppm/C; Value_Code: 510R; Value: 510; EIA_Code: E24; SizeX_mm: 1; SizeY_mm: 0.5; SizeZ_mm: 0.6; Value2: 0.063W; AEC Qualified: Y; VDC_V: 50V; AEC Category: Q200; AEC Grade: 0
R329 R367 R368 R370 = CMP-0026993-2: as R119 on sheet PROC074B_PWR_RST_LEDs
R364 R369 = CMP-0025958-3: RES, 10.0 k, 1%, 0.063 W, AEC-Q200 Grade 0, 0402; Manufacturer: Vishay-Dale; Power_W: 63mW; TempCo: 100 ppm/C; Value_Code: 10k0; Value: 10.0k; EIA_Code: E96; Res_ohm: 10k; SizeX_mm: 1; SizeY_mm: 0.5; SizeZ_mm: 0.6; Value2: 0.063W; AEC Qualified: Y; VDC_V: 50V; AEC Category: Q200; AEC Grade: 0
TP1 = CMP-0055138-1: Test Point, Miniature, Black, TH; Manufacturer: Keystone; CNHeader: FALSE; Green_Lifecycle: Active; Green_REACh: Passed; ContactFinish: Silver; CT: TRUE
U13 = CMP-0076352-4: 3.5A, 36 V Synchronous, 2.1MHz, Automotive Step Down DC-DC Converter, RNL0022A (VQFN-HR-22); Manufacturer: Texas Instruments; SizeX_mm: 4.0; SizeY_mm: 5.0; CompType: IC; SizeZ_mm: 0.9; SizeArea_mm2: 20.0; SizeAreaWB_mm2: 42.0; AEC Category: Q200; AEC Qualified: Y
U29 = CMP-0076347-4: 2.5A, 36 V Synchronous, 2.1MHz, Automotive Step Down DC-DC Converter, RNL0022A (VQFN-HR-22); Manufacturer: Texas Instruments; Alternate PartNumber: LM536255QRNLTQ1; SizeX_mm: 4.0; SizeY_mm: 5.0; CompType: IC; SizeZ_mm: 0.9; SizeArea_mm2: 20.0; SizeAreaWB_mm2: 42.0; AEC Category: Q200; AEC Qualified: Y
U31 U32 = CMP-0077265-1: 5.5-V, 2-A, 80 mohm Low Leakage Load Switch with RCB and Programmable Rise Time, DBV0006A (SOT-23-6); Alternate PartNumber: TPS22917DBVT; Alternate Manufacturer: Texas Instruments; SizeAreaWB_mm2: 14.82; SizeZ_mm: 1.45; SizeX_mm: 2.8; SizeY_mm: 2.9; SizeArea_mm2: 8.12; CompType: IC; AEC Qualified: N; AEC Category: Q200

## Sheet PROC074B_Current_Sensors.SchDoc
size 431 x 279 mm; Date: Not shown in title block; ApprovedBy: Not shown in title block; CheckedBy: Not shown in title block; Author: Not shown in title block; CompanyName: Not shown in title block; Engineer: Not shown in title block; Organization: Not shown in title block; Address1: Not shown in title block; Address2: Not shown in title block; Address3: Not shown in title block; Address4: Not shown in title block; DocumentNumber: 1; Revision: Use project parameter SCH_Rev; SheetNumber: 6; SheetTotal: 22; PageSetup: Record=PageOptions¦CenterHorizontal=True¦CenterVertical=True¦PrintScale=1.00¦XCorrection=1.00¦YCorrection=1.00¦PrintKind=0¦BorderSize=5000000¦LeftOffset=0¦BottomOffset=0¦Orientation=2¦PaperLength=1000¦PaperWidth=1000¦Scale=100¦PaperSource=15¦PrintQuality=600¦MediaType=1¦DitherType=10¦PaperKind=Letter¦PrintScaleMode=1
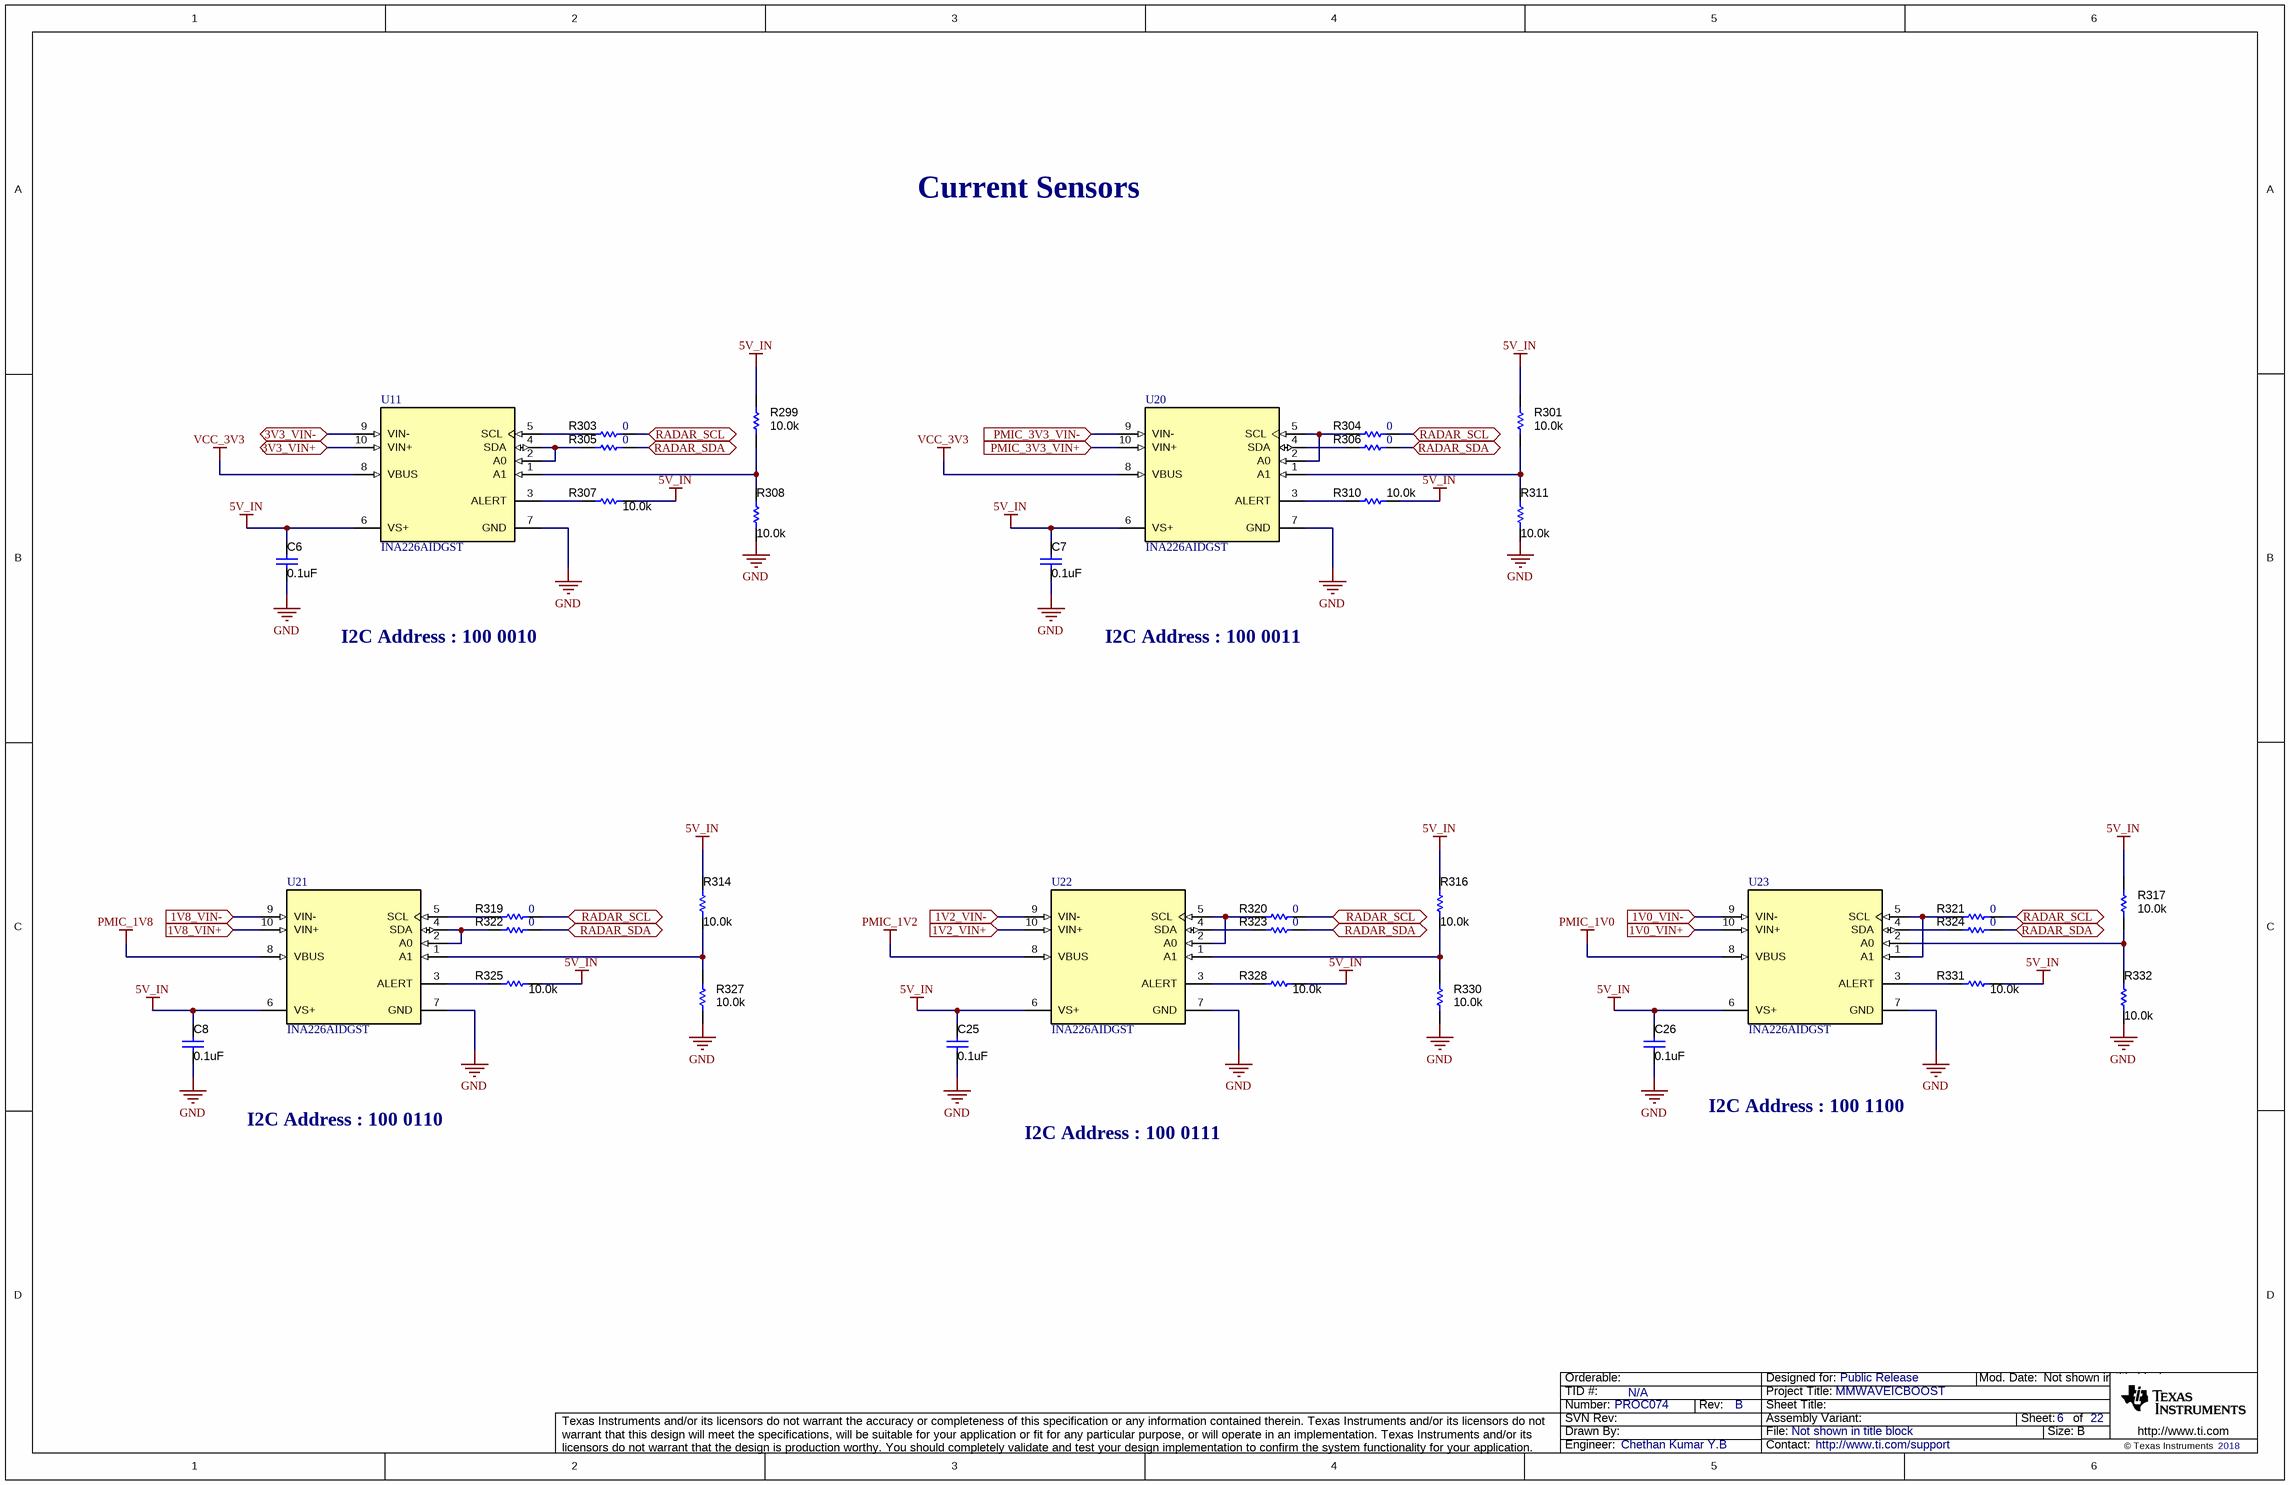
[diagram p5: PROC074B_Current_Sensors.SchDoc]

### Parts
C6  ValueDisplayed: 0.1uF  [0402L]  (hidden comment: CGA2B3X7R1H104K050BB)
C7  ValueDisplayed: 0.1uF  [0402L]  (hidden comment: CGA2B3X7R1H104K050BB)
C8  ValueDisplayed: 0.1uF  [0402L]  (hidden comment: CGA2B3X7R1H104K050BB)
C25  ValueDisplayed: 0.1uF  [0402L]  (hidden comment: CGA2B3X7R1H104K050BB)
C26  ValueDisplayed: 0.1uF  [0402L]  (hidden comment: CGA2B3X7R1H104K050BB)
R299  ValueDisplayed: 10.0k  [0402L]  (hidden comment: CRCW040210K0FKED)
R301  ValueDisplayed: 10.0k  [0402L]  (hidden comment: CRCW040210K0FKED)
R303  ValueDisplayed: 0  [0201]  (hidden comment: CRCW02010000Z0ED)
R304  ValueDisplayed: 0  [0201]  (hidden comment: CRCW02010000Z0ED)
R305  ValueDisplayed: 0  [0201]  (hidden comment: CRCW02010000Z0ED)
R306  ValueDisplayed: 0  [0201]  (hidden comment: CRCW02010000Z0ED)
R307  ValueDisplayed: 10.0k  [0402L]  (hidden comment: CRCW040210K0FKED)
R308  ValueDisplayed: 10.0k  [0402L]  (hidden comment: CRCW040210K0FKED)
R310  ValueDisplayed: 10.0k  [0402L]  (hidden comment: CRCW040210K0FKED)
R311  ValueDisplayed: 10.0k  [0402L]  (hidden comment: CRCW040210K0FKED)
R314  ValueDisplayed: 10.0k  [0402L]  (hidden comment: CRCW040210K0FKED)
R316  ValueDisplayed: 10.0k  [0402L]  (hidden comment: CRCW040210K0FKED)
R317  ValueDisplayed: 10.0k  [0402L]  (hidden comment: CRCW040210K0FKED)
R319  ValueDisplayed: 0  [0201]  (hidden comment: CRCW02010000Z0ED)
R320  ValueDisplayed: 0  [0201]  (hidden comment: CRCW02010000Z0ED)
R321  ValueDisplayed: 0  [0201]  (hidden comment: CRCW02010000Z0ED)
R322  ValueDisplayed: 0  [0201]  (hidden comment: CRCW02010000Z0ED)
R323  ValueDisplayed: 0  [0201]  (hidden comment: CRCW02010000Z0ED)
R324  ValueDisplayed: 0  [0201]  (hidden comment: CRCW02010000Z0ED)
R325  ValueDisplayed: 10.0k  [0402L]  (hidden comment: CRCW040210K0FKED)
R327  ValueDisplayed: 10.0k  [0402L]  (hidden comment: CRCW040210K0FKED)
R328  ValueDisplayed: 10.0k  [0402L]  (hidden comment: CRCW040210K0FKED)
R330  ValueDisplayed: 10.0k  [0402L]  (hidden comment: CRCW040210K0FKED)
R331  ValueDisplayed: 10.0k  [0402L]  (hidden comment: CRCW040210K0FKED)
R332  ValueDisplayed: 10.0k  [0402L]  (hidden comment: CRCW040210K0FKED)
U11  INA226AIDGST  [DGS0010A_L]
U20  INA226AIDGST  [DGS0010A_L]
U21  INA226AIDGST  [DGS0010A_L]
U22  INA226AIDGST  [DGS0010A_L]
U23  INA226AIDGST  [DGS0010A_L]

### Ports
1V0_VIN+ (in), 1V0_VIN- (in), 1V2_VIN+ (in), 1V2_VIN- (in), 1V8_VIN+ (in), 1V8_VIN- (in), 3V3_VIN+, 3V3_VIN-, PMIC_3V3_VIN+ (in), PMIC_3V3_VIN- (in), RADAR_SCL, RADAR_SDA

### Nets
5V_IN: C6.2 C7.2 C8.2 C25.2 C26.2 R299.2 R301.2 R307.1 R310.1 R314.2 R316.2 R317.2 R325.1 R328.1 R331.1 U11.6(VS+) U20.6(VS+) U21.6(VS+) U22.6(VS+) U23.6(VS+)
BRD_3V3: U11.9(VIN-) U20.9(VIN-) ; port 3V3_VIN-, port PMIC_3V3_VIN-
CB_PMIC_1V0: U23.9(VIN-) ; port 1V0_VIN-
CB_PMIC_1V2: U22.9(VIN-) ; port 1V2_VIN-
CB_PMIC_1V8: U21.9(VIN-) ; port 1V8_VIN-
GND: C6.1 C7.1 C8.1 C25.1 C26.1 R308.1 R311.1 R327.1 R330.1 R332.1 U11.7(GND) U20.7(GND) U21.7(GND) U22.7(GND) U23.7(GND)
PMIC_1V0: U23.8(VBUS) U23.10(VIN+) ; port 1V0_VIN+
PMIC_1V2: U22.8(VBUS) U22.10(VIN+) ; port 1V2_VIN+
PMIC_1V8: U21.8(VBUS) U21.10(VIN+) ; port 1V8_VIN+
PMIC_3V3: U20.10(VIN+) ; port PMIC_3V3_VIN+
VCC_3V3: U11.8(VBUS) U11.10(VIN+) U20.8(VBUS) ; port 3V3_VIN+
RADAR_SCL: R303.2 R304.2 R319.2 R320.2 R321.2 ; port RADAR_SCL
RADAR_SDA: R305.2 R306.2 R322.2 R323.2 R324.2 ; port RADAR_SDA
NetR299_1: R299.1 R308.2 U11.1(A1)
NetR301_1: R301.1 R311.2 U20.1(A1)
NetR303_1: R303.1 U11.5(SCL)
NetR304_1: R304.1 U20.2(A0) U20.5(SCL)
NetR305_1: R305.1 U11.2(A0) U11.4(SDA)
NetR306_1: R306.1 U20.4(SDA)
NetR307_2: R307.2 U11.3(ALERT)
NetR310_2: R310.2 U20.3(ALERT)
NetR314_1: R314.1 R327.2 U21.1(A1)
NetR316_1: R316.1 R330.2 U22.1(A1)
NetR317_1: R317.1 R332.2 U23.2(A0)
NetR319_1: R319.1 U21.5(SCL)
NetR320_1: R320.1 U22.2(A0) U22.5(SCL)
NetR321_1: R321.1 U23.1(A1) U23.5(SCL)
NetR322_1: R322.1 U21.2(A0) U21.4(SDA)
NetR323_1: R323.1 U22.4(SDA)
NetR324_1: R324.1 U23.4(SDA)
NetR325_2: R325.2 U21.3(ALERT)
NetR328_2: R328.2 U22.3(ALERT)
NetR331_2: R331.2 U23.3(ALERT)

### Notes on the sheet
- Current Sensors
- I2C Address : 100 0010
- I2C Address : 100 0011
- I2C Address : 100 0110
- I2C Address : 100 0111
- I2C Address : 100 1100

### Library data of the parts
C6-C8 C25 C26 = CMP-0006325-2: CAP, CERM, 0.1 uF, 50 V, +/- 10%, X7R, AEC-Q200 Grade 1, 0402; Manufacturer: TDK; TaMin_C: -55°C; ESR_ohm: 0.039064; Polarized: N; SizeAreaWB_mm2: 3; Value1: 0.039064 ohm; U/M: EA; Value: 0.1uF; TaMax_C: 125°C; SizeZ_mm: 0.6; SizeX_mm: 1; SizeY_mm: 0.5; Cap_Case: 0402; Value2: 50V; CompType: Capacitor; AEC Qualified: Y; Cap_F: 100nF; IRMS_A: 8.14669dA; AEC Category: Q200
R299 R301 R317 R327 R330 = CMP-0025958-2: RES, 10.0 k, 1%, 0.063 W, 0402; Manufacturer: Vishay-Dale; Power_W: 63mW; TempCo: 100 ppm/C; Value_Code: 10k0; U/M: EA; Value: 10.0k; EIA_Code: E96; Res_ohm: 10k; SizeX_mm: 1; SizeY_mm: 0.5; SizeZ_mm: 0.6; Value2: 0.063W; CompType: Resistor; VDC_V: 50V; AEC Category: Q200; INSTALLATION: DNP
R303 = CMP-0027008-4: RES, 0, 5%, 0.05 W, 0201; Manufacturer: Vishay-Dale; Power_W: 50mW; TempCo: ppm/C; Value_Code: 0000; Value: 0; EIA_Code: E24; SizeX_mm: 0.6; SizeY_mm: 0.3; SizeZ_mm: 0.26; Value2: 0.05W; SizeArea_mm2: 0.18; CompType: Resistor; AEC Qualified: N; AEC Category: Q200; INSTALLATION: DNP
R304-R306 R319-R324 = CMP-0027008-4: RES, 0, 5%, 0.05 W, 0201; Manufacturer: Vishay-Dale; Power_W: 50mW; TempCo: ppm/C; Value_Code: 0000; Value: 0; EIA_Code: E24; SizeX_mm: 0.6; SizeY_mm: 0.3; SizeZ_mm: 0.26; Value2: 0.05W; SizeArea_mm2: 0.18; AEC Qualified: N; AEC Category: Q200
R307 R308 R310 R311 R314 R316 R325 R328 R331 R332 = CMP-0025958-2: as R51 on sheet PROC074B_PWR_RST_LEDs
U11 U20-U23 = CMP-0037978-1: High-Side Measurement, Bi-Directional Current / Power Monitor with I2C Interface, 2.7 to 5.5 V, -40 to 125 degC, 10-pin SOP (DGS10), Green (RoHS & no Sb/Br); Vs(Min)(V): 2.7; Rating: Catalog; Quiescent Current (+/-)(Typ)(mA): 0.33; Input Offset (+/-)(Max)(uV): 10; CMRR(Min)(dB): 126; Vs(Max)(V): 5.5; Common Mode Range(Max)(V): 36; Input Offset Drift (+/-)(Max)(uV/Degrees Celsius): 0.1; Common Mode Range(Min)(V): 0; SubFamily: Current Shunt Monitor; Gain(V/V): 1; Small-Signal Bandwidth(Typ)(MHz): 0.007

## Sheet PROC074B_LP8752J_PMIC.SchDoc
size 431 x 279 mm; Date: Not shown in title block; ApprovedBy: Not shown in title block; CheckedBy: Not shown in title block; Author: Not shown in title block; CompanyName: Not shown in title block; Engineer: Not shown in title block; Organization: Not shown in title block; Address1: Not shown in title block; Address2: Not shown in title block; Address3: Not shown in title block; Address4: Not shown in title block; DocumentNumber: 1; Revision: Use project parameter SCH_Rev; SheetNumber: 7; SheetTotal: 22; PageSetup: Record=PageOptions¦CenterHorizontal=True¦CenterVertical=True¦PrintScale=1.00¦XCorrection=1.00¦YCorrection=1.00¦PrintKind=0¦BorderSize=5000000¦LeftOffset=0¦BottomOffset=0¦Orientation=2¦PaperLength=1000¦PaperWidth=1000¦Scale=100¦PaperSource=15¦PrintQuality=600¦MediaType=1¦DitherType=10¦PaperKind=Letter¦PrintScaleMode=1
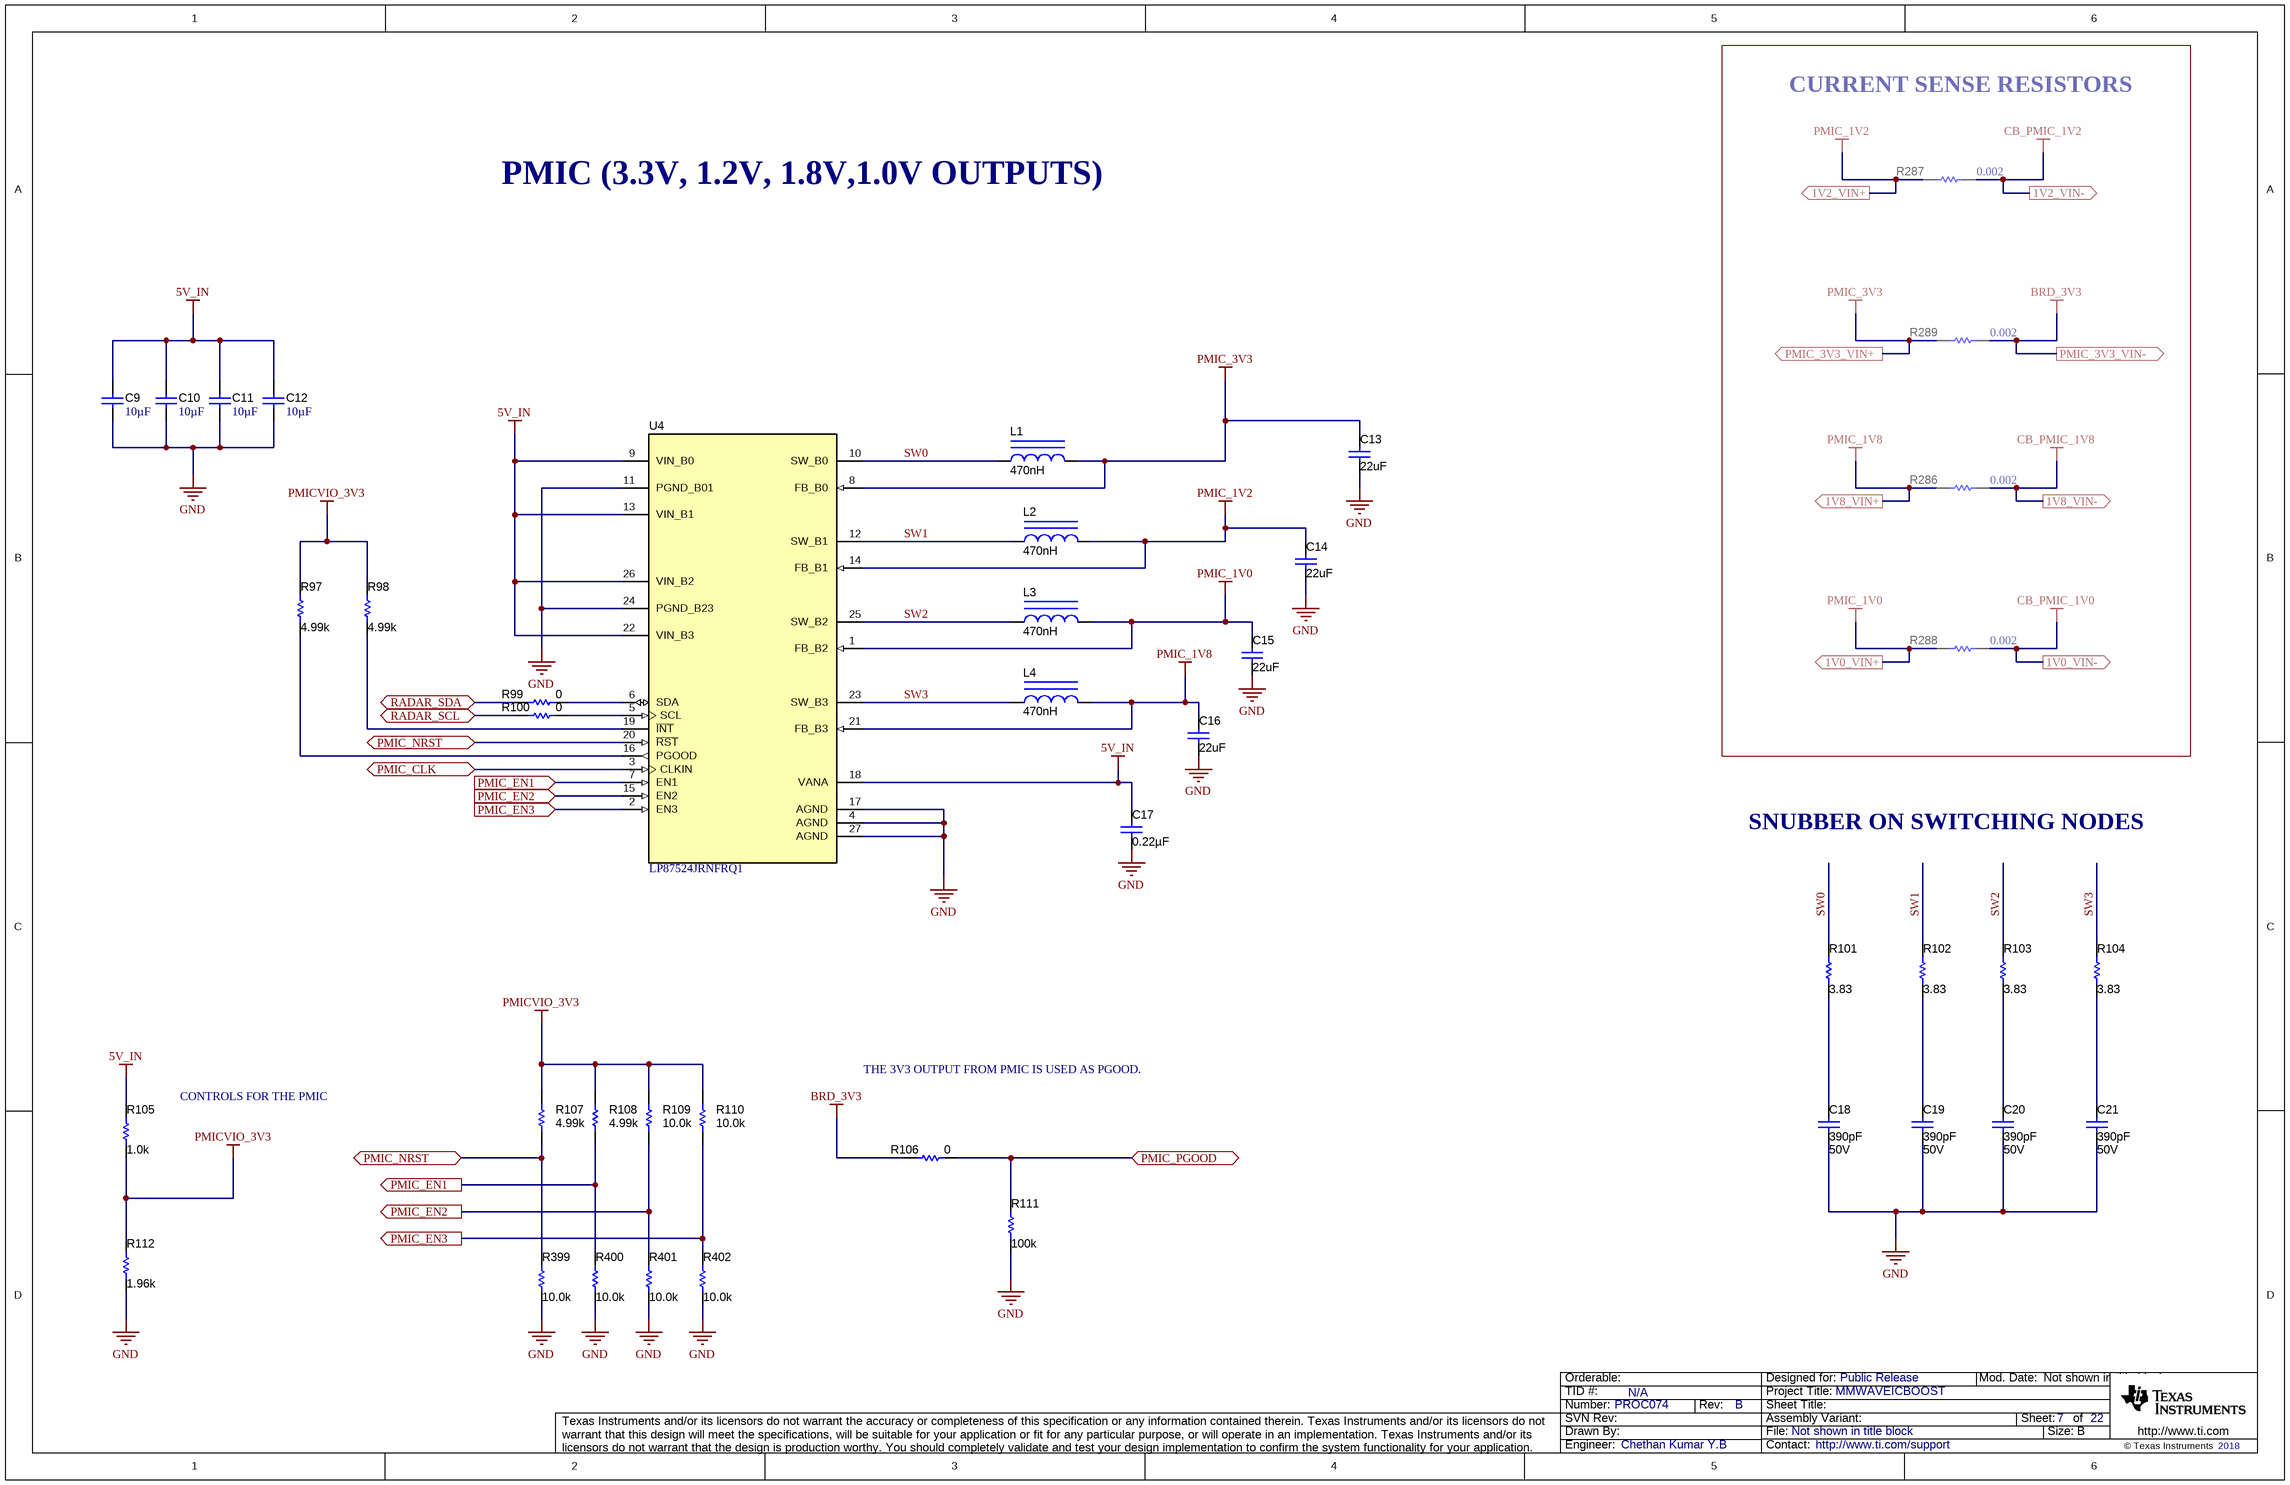
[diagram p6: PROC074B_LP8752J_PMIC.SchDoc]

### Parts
C9  ValueDisplayed: 10µF  [0805_HV]  (hidden comment: GRM21BR71A106KA73L)
C10  ValueDisplayed: 10µF  [0805_HV]  (hidden comment: GRM21BR71A106KA73L)
C11  ValueDisplayed: 10µF  [0805_HV]  (hidden comment: GRM21BR71A106KA73L)
C12  ValueDisplayed: 10µF  [0805_HV]  (hidden comment: GRM21BR71A106KA73L)
C13  ValueDisplayed: 22uF  [1206_180]  (hidden comment: GCM31CR71A226KE02)
C14  ValueDisplayed: 22uF  [1206_180]  (hidden comment: GCM31CR71A226KE02)
C15  ValueDisplayed: 22uF  [1206_180]  (hidden comment: GCM31CR71A226KE02)
C16  ValueDisplayed: 22uF  [1206_180]  (hidden comment: GCM31CR71A226KE02)
C17  ValueDisplayed: 0.22µF  [0402L]  (hidden comment: GCM155R71C224KE02D)
C18  VDC_V: 50V  ValueDisplayed: 390pF  [0402L]  (hidden comment: CGA2B2NP01H391J050BA)
C19  VDC_V: 50V  ValueDisplayed: 390pF  [0402L]  (hidden comment: CGA2B2NP01H391J050BA)
C20  VDC_V: 50V  ValueDisplayed: 390pF  [0402L]  (hidden comment: CGA2B2NP01H391J050BA)
C21  VDC_V: 50V  ValueDisplayed: 390pF  [0402L]  (hidden comment: CGA2B2NP01H391J050BA)
L1  ValueDisplayed: 470nH  [DFE252012P]  (hidden comment: DFE252012P-R47M=P2)
L2  ValueDisplayed: 470nH  [DFE252012P]  (hidden comment: DFE252012P-R47M=P2)
L3  ValueDisplayed: 470nH  [DFE252012P]  (hidden comment: DFE252012P-R47M=P2)
L4  ValueDisplayed: 470nH  [DFE252012P]  (hidden comment: DFE252012P-R47M=P2)
R97  ValueDisplayed: 4.99k  [0402L]  (hidden comment: CRCW04024K99FKED)
R98  ValueDisplayed: 4.99k  [0402L]  (hidden comment: CRCW04024K99FKED)
R99  ValueDisplayed: 0  [0201_Silk]  (hidden comment: CRCW02010000Z0ED)
R100  ValueDisplayed: 0  [0201_Silk]  (hidden comment: CRCW02010000Z0ED)
R101  ValueDisplayed: 3.83  [0402L]  (hidden comment: CRCW04023R83FKED)
R102  ValueDisplayed: 3.83  [0402L]  (hidden comment: CRCW04023R83FKED)
R103  ValueDisplayed: 3.83  [0402L]  (hidden comment: CRCW04023R83FKED)
R104  ValueDisplayed: 3.83  [0402L]  (hidden comment: CRCW04023R83FKED)
R105  ValueDisplayed: 1.0k  [0402L]  (hidden comment: ERJ-2GEJ102X)
R106  ValueDisplayed: 0  [0402L]  (hidden comment: ERJ-2GE0R00X)
R107  ValueDisplayed: 4.99k  [0402L]  (hidden comment: ERJ-2RKF4991X)
R108  ValueDisplayed: 4.99k  [0402L]  (hidden comment: ERJ-2RKF4991X)
R109  ValueDisplayed: 10.0k  [0402L]  (hidden comment: CRCW040210K0FKED)
R110  ValueDisplayed: 10.0k  [0402L]  (hidden comment: CRCW040210K0FKED)
R111  ValueDisplayed: 100k  [0402L]  (hidden comment: CRCW0402100KFKED)
R112  ValueDisplayed: 1.96k  [0402L]  (hidden comment: CRCW04021K96FKED)
R286  ValueDisplayed: 0.002  [1206]  (hidden comment: PMR18EZPFV2L00)
R287  ValueDisplayed: 0.002  [1206]  (hidden comment: PMR18EZPFV2L00)
R288  ValueDisplayed: 0.002  [1206]  (hidden comment: PMR18EZPFV2L00)
R289  ValueDisplayed: 0.002  [1206]  (hidden comment: PMR18EZPFV2L00)
R399  ValueDisplayed: 10.0k  [0402L]  (hidden comment: CRCW040210K0FKED)
R400  ValueDisplayed: 10.0k  [0402L]  (hidden comment: CRCW040210K0FKED)
R401  ValueDisplayed: 10.0k  [0402L]  (hidden comment: CRCW040210K0FKED)
R402  ValueDisplayed: 10.0k  [0402L]  (hidden comment: CRCW040210K0FKED)
U4  LP87524JRNFRQ1  [RNF0026C]

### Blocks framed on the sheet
CURRENT SENSE RESISTORS: R286-R289

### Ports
1V0_VIN+ (out), 1V0_VIN- (out), 1V2_VIN+ (out), 1V2_VIN- (out), 1V8_VIN+ (out), 1V8_VIN- (out), PMIC_3V3_VIN+ (out), PMIC_3V3_VIN- (out), PMIC_CLK, PMIC_EN1 (in), PMIC_EN1 (out), PMIC_EN2 (in), PMIC_EN2 (out), PMIC_EN3 (in), PMIC_EN3 (out), PMIC_NRST, PMIC_PGOOD, RADAR_SCL, RADAR_SDA

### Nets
5V_IN: C9.2 C10.2 C11.2 C12.2 C17.2 R105.2 U4.9(VIN_B0) U4.13(VIN_B1) U4.18(VANA) U4.22(VIN_B3) U4.26(VIN_B2)
BRD_3V3: R106.1 R289.2 ; port PMIC_3V3_VIN-
CB_PMIC_1V0: R288.2 ; port 1V0_VIN-
CB_PMIC_1V2: R287.2 ; port 1V2_VIN-
CB_PMIC_1V8: R286.2 ; port 1V8_VIN-
GND: C9.1 C10.1 C11.1 C12.1 C13.1 C14.1 C15.1 C16.1 C17.1 C18.1 C19.1 C20.1 C21.1 R111.1 R112.1 R399.1 R400.1 R401.1 R402.1 U4.4(AGND) U4.11(PGND_B01) U4.17(AGND) U4.24(PGND_B23) U4.27(AGND)
PMIC_1V0: C15.2 L3.2 R288.1 U4.1(FB_B2) ; port 1V0_VIN+
PMIC_1V2: C14.2 L2.2 R287.1 U4.14(FB_B1) ; port 1V2_VIN+
PMIC_1V8: C16.2 L4.2 R286.1 U4.21(FB_B3) ; port 1V8_VIN+
PMIC_3V3: C13.2 L1.2 R289.1 U4.8(FB_B0) ; port PMIC_3V3_VIN+
PMICVIO_3V3: R97.2 R98.2 R105.1 R107.1 R108.2 R109.2 R110.2 R112.2
PMIC_CLK: U4.3(CLKIN) ; port PMIC_CLK
PMIC_EN1: R108.1 R400.2 U4.7(EN1) ; port PMIC_EN1
PMIC_EN2: R109.1 R401.2 U4.15(EN2) ; port PMIC_EN2
PMIC_EN3: R110.1 R402.2 U4.2(EN3) ; port PMIC_EN3
PMIC_NRST: R107.2 R399.2 U4.20(~{RST}) ; port PMIC_NRST
PMIC_PGOOD: R106.2 R111.2 ; port PMIC_PGOOD
RADAR_SCL: R100.2 ; port RADAR_SCL
RADAR_SDA: R99.2 ; port RADAR_SDA
SW0: L1.1 R101.2 U4.10(SW_B0)
SW1: L2.1 R102.2 U4.12(SW_B1)
SW2: L3.1 R103.2 U4.25(SW_B2)
SW3: L4.1 R104.2 U4.23(SW_B3)
NetC18_2: C18.2 R101.1
NetC19_2: C19.2 R102.1
NetC20_2: C20.2 R103.1
NetC21_2: C21.2 R104.1
NetR97_1: R97.1 U4.16(PGOOD)
NetR98_1: R98.1 U4.19(~{INT})
NetR99_1: R99.1 U4.6(SDA)
NetR100_1: R100.1 U4.5(SCL)

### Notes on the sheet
- PMIC (3.3V, 1.2V, 1.8V,1.0V OUTPUTS)
- SNUBBER ON SWITCHING NODES
- CONTROLS FOR THE PMIC
- THE 3V3 OUTPUT FROM PMIC IS USED AS PGOOD.

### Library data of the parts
C9-C12 = CMP-0081849-1: CAP, CERM, 10 µF,  V,+/- 10%, X7R, 0805; Manufacturer: MuRata; TaMin_C: -55°C; Polarized: N; Green_Lifecycle: Active; SizeAreaWB_mm2: 6.75; Green_REACh: Passed; U/M: EA; Value: 10uF; TaMax_C: 125°C; SizeZ_mm: 1.45; SizeX_mm: 2; SizeY_mm: 1.25; Cap_Case: 0805; SizeArea_mm2: 2.5; AEC Category: Q200
C13-C16 = CMP-0008811-2: CAP, CERM, 22 uF, 10 V, +/- 10%, X7R, AEC-Q200 Grade 1, 1206; Manufacturer: MuRata; TaMin_C: -55°C; Polarized: N; SizeAreaWB_mm2: 10.92; Value1: Unknown; U/M: EA; Value: 22uF; TaMax_C: 125°C; SizeZ_mm: 1.8; SizeX_mm: 3.2; SizeY_mm: 1.6; Cap_Case: 1206; Value2: 10V; SizeArea_mm2: 5.12; CompType: Capacitor; AEC Qualified: Y; Cap_F: 22µF; AEC Grade: 1; AEC Category: Q200
C17 = CMP-0078265-1: CAP, CERM, 0.22 µF, 16 V,+/- 10%, X7R, AEC-Q200 Grade 1, 0402; Manufacturer: MuRata; TaMin_C: -55°C; Polarized: N; SizeAreaWB_mm2: 3; U/M: EA; Value: 0.22uF; TaMax_C: 125°C; SizeZ_mm: 0.6; SizeX_mm: 1; SizeY_mm: 0.5; Cap_Case: 0402; Value2: 16V; CompType: Capacitor; AEC Qualified: Y; Cap_F: 220nF; AEC Category: Q200
C18-C21 = CMP-0078223-1: CAP, CERM, 390 pF, 50 V,+/- 5%, C0G/NP0, AEC-Q200 Grade 0, 0402; Manufacturer: TDK; TaMin_C: -55°C; Polarized: N; SizeAreaWB_mm2: 3; U/M: EA; Value: 390pF; TaMax_C: 150°C; SizeZ_mm: 0.6; SizeX_mm: 1; SizeY_mm: 0.5; Cap_Case: 0402; AEC Qualified: Y; AEC Grade: 0; AEC Category: Q200
L1-L4 = CMP-0058946-1: Inductor, Shielded, 470 nH, 4.7 A, 0.021 ohm, SMD; Manufacturer: MuRata Toko; Isat: 6.4A @ 30% inductance drop; Irms: 4.7A @ 40C rise; SizeAreaWB_mm2: 10.5; DCR_ohm: 0.021; Value: 470nH; Imax_A: 4.7A; SizeZ_mm: 1.2; SizeX_mm: 2.5; SizeY_mm: 2; SizeArea_mm2: 5; AEC Category: Q200
R97 R98 = CMP-0026414-1: RES, 4.99 k, 1%, 0.063 W, 0402; Manufacturer: Vishay-Dale; Power_W: 63mW; TempCo: 100 ppm/C; Value_Code: 4k99; U/M: EA; Value: 4.99k; EIA_Code: E96; SizeX_mm: 1; SizeY_mm: 0.5; SizeZ_mm: 0.6; Value2: 0.063W; VDC_V: 50V; AEC Category: Q200
R99 R100 = CMP-0027008-3: as R121 on sheet PROC074B_PWR_RST_LEDs
R101-R104 = CMP-0026363-1: RES, 3.83, 1%, 0.063 W, 0402; Manufacturer: Vishay-Dale; Power_W: 63mW; TempCo: 100 ppm/C; Value_Code: 3R83; U/M: EA; Value: 3.83; EIA_Code: E96; SizeX_mm: 1; SizeY_mm: 0.5; SizeZ_mm: 0.6; Value2: 0.063W; VDC_V: 50V; AEC Category: Q200
R105 = CMP-0078193-1: RES, 1.0 k, 5%, 0.1 W, AEC-Q200 Grade 0, 0402; Manufacturer: Panasonic; Value_Code: 1k00; SizeArea_mm2: 0.5; AEC Qualified: Y; AEC Category: Q200; Res_ohm: 1k; Value: 1.0k; SizeZ_mm: 0.6; Green_REACh: Passed; EIA_Code: E24; TempCo: 200 ppm/C; AEC Grade: 0; Power_W: 100mW; VDC_V: 50V; Value2: 0.1W; Green_Lifecycle: Active; U/M: EA; SizeX_mm: 1
R106 = CMP-0026992-2: as R74 on sheet PROC074B_PWR_RST_LEDs
R107 R108 = CMP-0026701-1: RES, 4.99 k, 1%, 0.1 W, AEC-Q200 Grade 0, 0402; Manufacturer: Panasonic; Power_W: 100mW; TempCo: 100 ppm/C; Value_Code: 4k99; U/M: EA; Value: 4.99k; EIA_Code: E96; SizeX_mm: 1; SizeY_mm: 0.5; SizeZ_mm: 0.6; Value2: 0.1W; CompType: Resistor; AEC Qualified: Y; VDC_V: 50V; AEC Grade: 0; AEC Category: Q200; INSTALLATION: DNP
R109 R110 = CMP-0025958-2: as R299 on sheet PROC074B_Current_Sensors
R111 = CMP-0025950-2: as R130 on sheet PROC074B_PWR_RST_LEDs
R112 = CMP-0026099-1: RES, 1.96 k, 1%, 0.063 W, 0402; Manufacturer: Vishay-Dale; Power_W: 63mW; TempCo: 100 ppm/C; Value_Code: 1k96; U/M: EA; Value: 1.96k; EIA_Code: E96; SizeX_mm: 1; SizeY_mm: 0.5; SizeZ_mm: 0.6; Value2: 0.063W; CompType: Resistor; VDC_V: 50V; AEC Category: Q200
R286-R289 = CMP-0081623-1: as R49 on sheet PROC074B_PWR_INPUT_REG
R399-R402 = CMP-0025958-2: as R51 on sheet PROC074B_PWR_RST_LEDs
U4 = CMP-0079120-1: 4-A + 2.5-A + Two 1.5-A Buck Converters With Integrated Switches, RNF0026C (VQFN-HR-26); Alternate PartNumber: LP87524JRNFTQ1; Alternate Manufacturer: Texas Instruments; SizeAreaWB_mm2: 27.5; SizeZ_mm: 0.9; SizeX_mm: 4; SizeY_mm: 4.5; SizeArea_mm2: 18; CompType: IC; AEC Qualified: Y; AEC Category: Q200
